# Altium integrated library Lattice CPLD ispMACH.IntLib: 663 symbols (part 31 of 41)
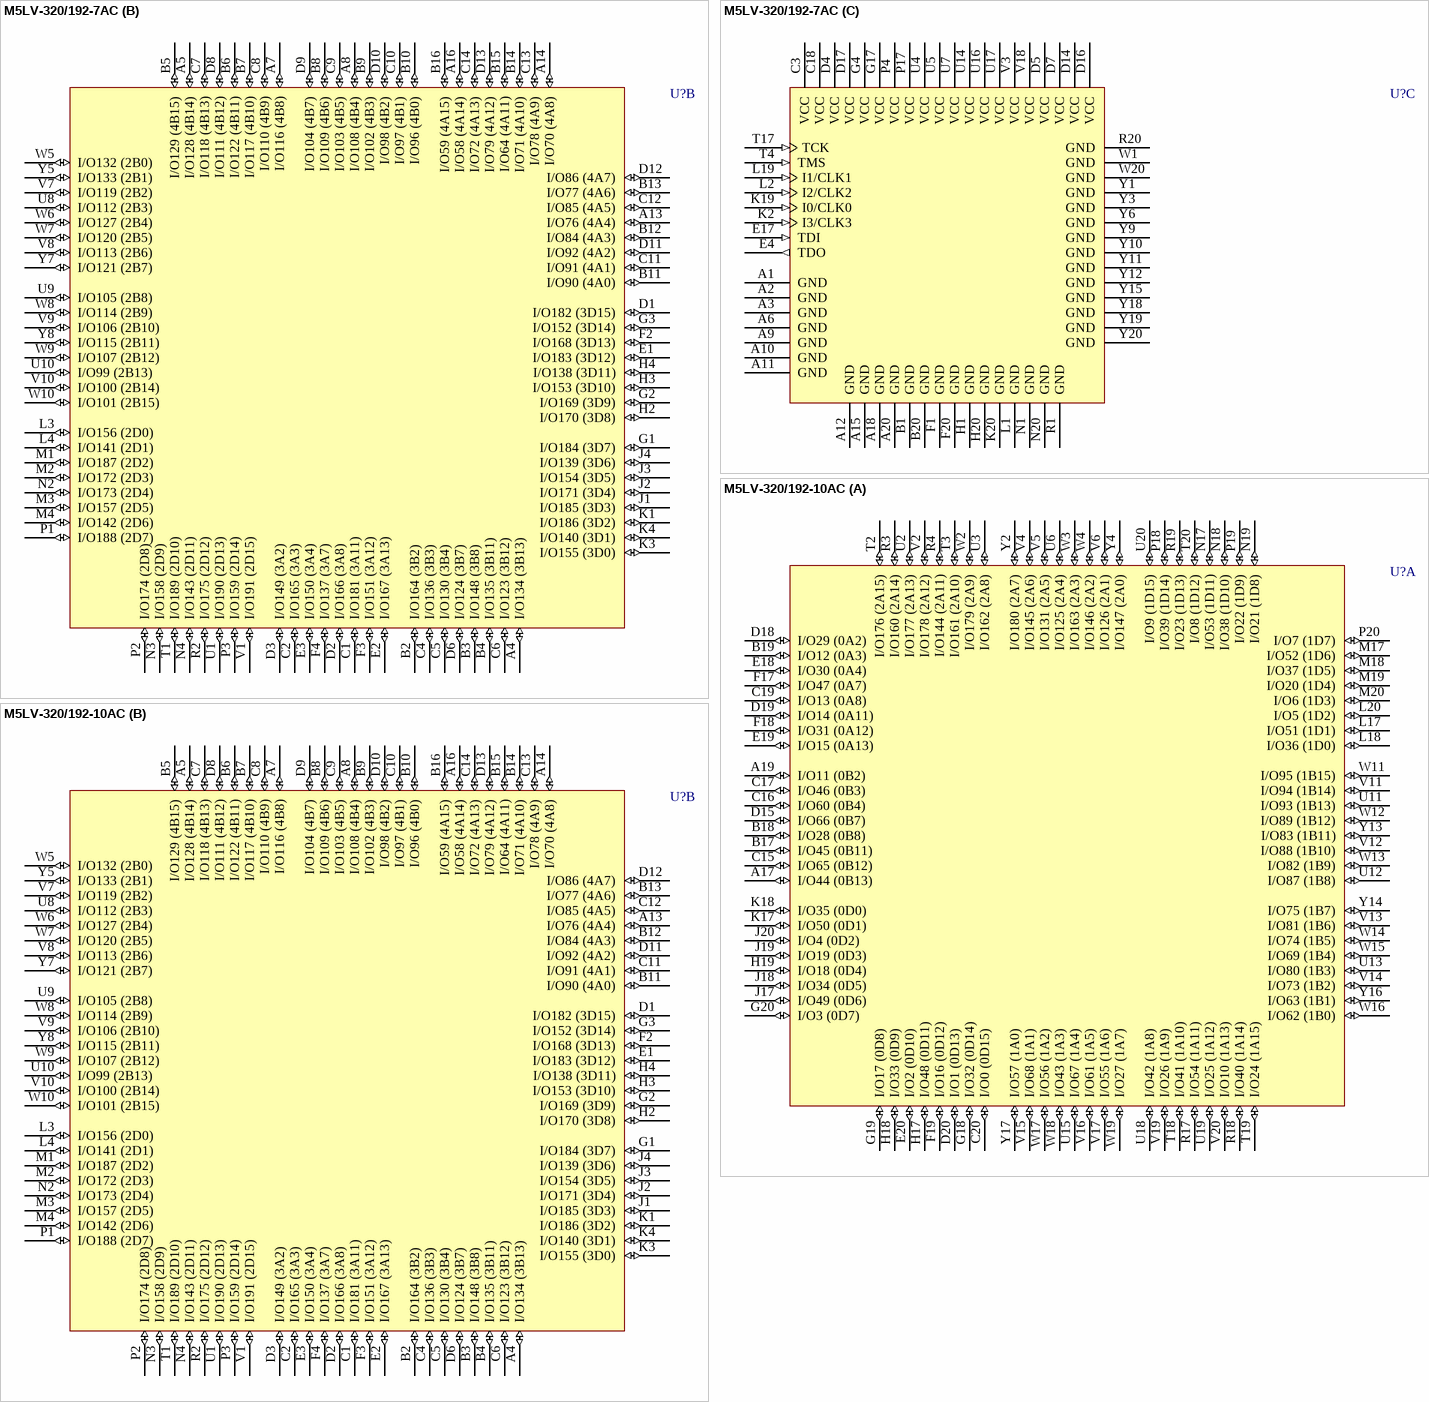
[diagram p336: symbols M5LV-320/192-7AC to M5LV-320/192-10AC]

## M5LV-320/192-7AC
designator U?
High-Density and High-I/O Complex PLD
footprint SBGA256 (BGA, 256-Leads, Body 27x27mm, Pitch 1.27mm)
3D model M5LV-SBGA256 (256-Ball Super Ball Grid Array (SBGA256))
part A pins: A17 I/O44 (0B13) (io), A19 I/O11 (0B2) (io), B17 I/O45 (0B11) (io), B18 I/O28 (0B8) (io), B19 I/O12 (0A3) (io), C15 I/O65 (0B12) (io), C16 I/O60 (0B4) (io), C17 I/O46 (0B3) (io), C19 I/O13 (0A8) (io), C20 I/O0 (0D15) (io), D15 I/O66 (0B7) (io), D18 I/O29 (0A2) (io), D19 I/O14 (0A11) (io), D20 I/O1 (0D13) (io), E18 I/O30 (0A4) (io), E19 I/O15 (0A13) (io), E20 I/O2 (0D10) (io), F17 I/O47 (0A7) (io), F18 I/O31 (0A12) (io), F19 I/O16 (0D12) (io), G18 I/O32 (0D14) (io), G19 I/O17 (0D8) (io), G20 I/O3 (0D7) (io), H17 I/O48 (0D11) (io), H18 I/O33 (0D9) (io), H19 I/O18 (0D4) (io), J17 I/O49 (0D6) (io), J18 I/O34 (0D5) (io), J19 I/O19 (0D3) (io), J20 I/O4 (0D2) (io), K17 I/O50 (0D1) (io), K18 I/O35 (0D0) (io), L17 I/O51 (1D1) (io), L18 I/O36 (1D0) (io), L20 I/O5 (1D2) (io), M17 I/O52 (1D6) (io), M18 I/O37 (1D5) (io), M19 I/O20 (1D4) (io), M20 I/O6 (1D3) (io), N17 I/O53 (1D11) (io), N18 I/O38 (1D10) (io), N19 I/O21 (1D8) (io), P18 I/O39 (1D14) (io), P19 I/O22 (1D9) (io), P20 I/O7 (1D7) (io), R3 I/O160 (2A14) (io), R4 I/O144 (2A11) (io), R17 I/O54 (1A11) (io), R18 I/O40 (1A14) (io), R19 I/O23 (1D13) (io), T2 I/O176 (2A15) (io), T3 I/O161 (2A10) (io), T18 I/O41 (1A10) (io), T19 I/O24 (1A15) (io), T20 I/O8 (1D12) (io), U2 I/O177 (2A13) (io), U3 I/O162 (2A8) (io), U6 I/O125 (2A4) (io), U11 I/O93 (1B13) (io), U12 I/O87 (1B8) (io), U13 I/O80 (1B3) (io), U15 I/O67 (1A4) (io), U18 I/O42 (1A8) (io), U19 I/O25 (1A12) (io), U20 I/O9 (1D15) (io), V2 I/O178 (2A12) (io), V4 I/O145 (2A6) (io), V5 I/O131 (2A5) (io), V6 I/O126 (2A1) (io), V11 I/O94 (1B14) (io), V12 I/O88 (1B10) (io), V13 I/O81 (1B6) (io), V14 I/O73 (1B2) (io), V15 I/O68 (1A1) (io), V16 I/O61 (1A5) (io), V17 I/O55 (1A6) (io), V19 I/O26 (1A9) (io), V20 I/O10 (1A13) (io), W2 I/O179 (2A9) (io), W3 I/O163 (2A3) (io), W4 I/O146 (2A2) (io), W11 I/O95 (1B15) (io), W12 I/O89 (1B12) (io), W13 I/O82 (1B9) (io), W14 I/O74 (1B5) (io), W15 I/O69 (1B4) (io), W16 I/O62 (1B0) (io), W17 I/O56 (1A2) (io), W18 I/O43 (1A3) (io), W19 I/O27 (1A7) (io), Y2 I/O180 (2A7) (io), Y4 I/O147 (2A0) (io), Y13 I/O83 (1B11) (io), Y14 I/O75 (1B7) (io), Y16 I/O63 (1B1) (io), Y17 I/O57 (1A0) (io)
part B pins: A4 I/O134 (3B13) (io), A5 I/O128 (4B14) (io), A7 I/O116 (4B8) (io), A8 I/O108 (4B4) (io), A13 I/O76 (4A4) (io), A14 I/O70 (4A8) (io), A16 I/O58 (4A14) (io), B2 I/O164 (3B2) (io), B3 I/O148 (3B8) (io), B4 I/O135 (3B11) (io), B5 I/O129 (4B15) (io), B6 I/O122 (4B11) (io), B7 I/O117 (4B10) (io), B8 I/O109 (4B6) (io), B9 I/O102 (4B3) (io), B10 I/O96 (4B0) (io), B11 I/O90 (4A0) (io), B12 I/O84 (4A3) (io), B13 I/O77 (4A6) (io), B14 I/O71 (4A10) (io), B15 I/O64 (4A11) (io), B16 I/O59 (4A15) (io), C1 I/O181 (3A11) (io), C2 I/O165 (3A3) (io), C4 I/O136 (3B3) (io), C5 I/O130 (3B4) (io), C6 I/O123 (3B12) (io), C7 I/O118 (4B13) (io), C8 I/O110 (4B9) (io), C9 I/O103 (4B5) (io), C10 I/O97 (4B1) (io), C11 I/O91 (4A1) (io), C12 I/O85 (4A5) (io), C13 I/O78 (4A9) (io), C14 I/O72 (4A13) (io), D1 I/O182 (3D15) (io), D2 I/O166 (3A8) (io), D3 I/O149 (3A2) (io), D6 I/O124 (3B7) (io), D8 I/O111 (4B12) (io), D9 I/O104 (4B7) (io), D10 I/O98 (4B2) (io), D11 I/O92 (4A2) (io), D12 I/O86 (4A7) (io), D13 I/O79 (4A12) (io), E1 I/O183 (3D12) (io), E2 I/O167 (3A13) (io), E3 I/O150 (3A4) (io), F2 I/O168 (3D13) (io), F3 I/O151 (3A12) (io), F4 I/O137 (3A7) (io), G1 I/O184 (3D7) (io), G2 I/O169 (3D9) (io), G3 I/O152 (3D14) (io), H2 I/O170 (3D8) (io), H3 I/O153 (3D10) (io), H4 I/O138 (3D11) (io), J1 I/O185 (3D3) (io), J2 I/O171 (3D4) (io), J3 I/O154 (3D5) (io), J4 I/O139 (3D6) (io), K1 I/O186 (3D2) (io), K3 I/O155 (3D0) (io), K4 I/O140 (3D1) (io), L3 I/O156 (2D0) (io), L4 I/O141 (2D1) (io), M1 I/O187 (2D2) (io), M2 I/O172 (2D3) (io), M3 I/O157 (2D5) (io), M4 I/O142 (2D6) (io), N2 I/O173 (2D4) (io), N3 I/O158 (2D9) (io), N4 I/O143 (2D11) (io), P1 I/O188 (2D7) (io), P2 I/O174 (2D8) (io), P3 I/O159 (2D14) (io), R2 I/O175 (2D12) (io), T1 I/O189 (2D10) (io), U1 I/O190 (2D13) (io), U8 I/O112 (2B3) (io), U9 I/O105 (2B8) (io), U10 I/O99 (2B13) (io), V1 I/O191 (2D15) (io), V7 I/O119 (2B2) (io), V8 I/O113 (2B6) (io), V9 I/O106 (2B10) (io), V10 I/O100 (2B14) (io), W5 I/O132 (2B0) (io), W6 I/O127 (2B4) (io), W7 I/O120 (2B5) (io), W8 I/O114 (2B9) (io), W9 I/O107 (2B12) (io), W10 I/O101 (2B15) (io), Y5 I/O133 (2B1) (io), Y7 I/O121 (2B7) (io), Y8 I/O115 (2B11) (io)
part C pins: A1 GND (power), A2 GND (power), A3 GND (power), A6 GND (power), A9 GND (power), A10 GND (power), A11 GND (power), A12 GND (power), A15 GND (power), A18 GND (power), A20 GND (power), B1 GND (power), B20 GND (power), C3 VCC (power), C18 VCC (power), D4 VCC (power), D5 VCC (power), D7 VCC (power), D14 VCC (power), D16 VCC (power), D17 VCC (power), E4 TDO (out), E17 TDI (in), F1 GND (power), F20 GND (power), G4 VCC (power), G17 VCC (power), H1 GND (power), H20 GND (power), K2 I3/CLK3 (in), K19 I0/CLK0 (in), K20 GND (power), L1 GND (power), L2 I2/CLK2 (in), L19 I1/CLK1 (in), N1 GND (power), N20 GND (power), P4 VCC (power), P17 VCC (power), R1 GND (power), R20 GND (power), T4 TMS (in), T17 TCK (in), U4 VCC (power), U5 VCC (power), U7 VCC (power), U14 VCC (power), U16 VCC (power), U17 VCC (power), V3 VCC (power), V18 VCC (power), W1 GND (power), W20 GND (power), Y1 GND (power), Y3 GND (power), Y6 GND (power), Y9 GND (power), Y10 GND (power), Y11 GND (power), Y12 GND (power), Y15 GND (power), Y18 GND (power), Y19 GND (power), Y20 GND (power)

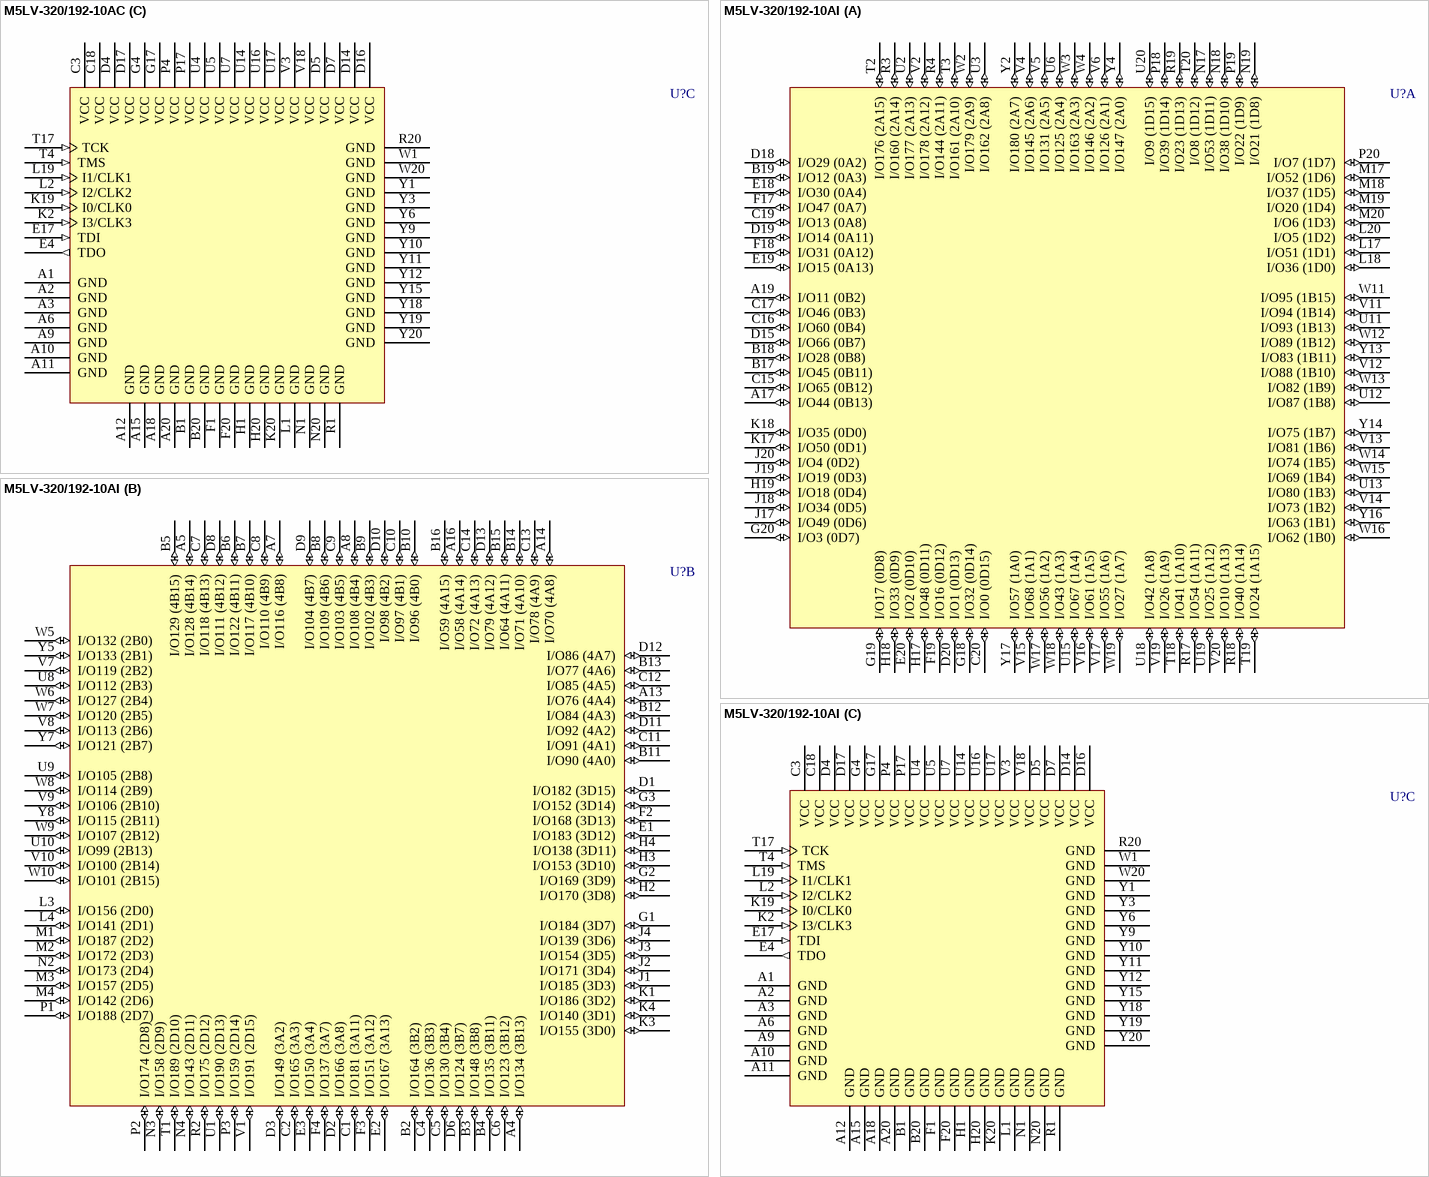
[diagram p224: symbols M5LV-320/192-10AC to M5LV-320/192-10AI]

## M5LV-320/192-10AC
designator U?
High-Density and High-I/O Complex PLD
footprint SBGA256 (BGA, 256-Leads, Body 27x27mm, Pitch 1.27mm)
3D model M5LV-SBGA256 (256-Ball Super Ball Grid Array (SBGA256))
part A pins: A17 I/O44 (0B13) (io), A19 I/O11 (0B2) (io), B17 I/O45 (0B11) (io), B18 I/O28 (0B8) (io), B19 I/O12 (0A3) (io), C15 I/O65 (0B12) (io), C16 I/O60 (0B4) (io), C17 I/O46 (0B3) (io), C19 I/O13 (0A8) (io), C20 I/O0 (0D15) (io), D15 I/O66 (0B7) (io), D18 I/O29 (0A2) (io), D19 I/O14 (0A11) (io), D20 I/O1 (0D13) (io), E18 I/O30 (0A4) (io), E19 I/O15 (0A13) (io), E20 I/O2 (0D10) (io), F17 I/O47 (0A7) (io), F18 I/O31 (0A12) (io), F19 I/O16 (0D12) (io), G18 I/O32 (0D14) (io), G19 I/O17 (0D8) (io), G20 I/O3 (0D7) (io), H17 I/O48 (0D11) (io), H18 I/O33 (0D9) (io), H19 I/O18 (0D4) (io), J17 I/O49 (0D6) (io), J18 I/O34 (0D5) (io), J19 I/O19 (0D3) (io), J20 I/O4 (0D2) (io), K17 I/O50 (0D1) (io), K18 I/O35 (0D0) (io), L17 I/O51 (1D1) (io), L18 I/O36 (1D0) (io), L20 I/O5 (1D2) (io), M17 I/O52 (1D6) (io), M18 I/O37 (1D5) (io), M19 I/O20 (1D4) (io), M20 I/O6 (1D3) (io), N17 I/O53 (1D11) (io), N18 I/O38 (1D10) (io), N19 I/O21 (1D8) (io), P18 I/O39 (1D14) (io), P19 I/O22 (1D9) (io), P20 I/O7 (1D7) (io), R3 I/O160 (2A14) (io), R4 I/O144 (2A11) (io), R17 I/O54 (1A11) (io), R18 I/O40 (1A14) (io), R19 I/O23 (1D13) (io), T2 I/O176 (2A15) (io), T3 I/O161 (2A10) (io), T18 I/O41 (1A10) (io), T19 I/O24 (1A15) (io), T20 I/O8 (1D12) (io), U2 I/O177 (2A13) (io), U3 I/O162 (2A8) (io), U6 I/O125 (2A4) (io), U11 I/O93 (1B13) (io), U12 I/O87 (1B8) (io), U13 I/O80 (1B3) (io), U15 I/O67 (1A4) (io), U18 I/O42 (1A8) (io), U19 I/O25 (1A12) (io), U20 I/O9 (1D15) (io), V2 I/O178 (2A12) (io), V4 I/O145 (2A6) (io), V5 I/O131 (2A5) (io), V6 I/O126 (2A1) (io), V11 I/O94 (1B14) (io), V12 I/O88 (1B10) (io), V13 I/O81 (1B6) (io), V14 I/O73 (1B2) (io), V15 I/O68 (1A1) (io), V16 I/O61 (1A5) (io), V17 I/O55 (1A6) (io), V19 I/O26 (1A9) (io), V20 I/O10 (1A13) (io), W2 I/O179 (2A9) (io), W3 I/O163 (2A3) (io), W4 I/O146 (2A2) (io), W11 I/O95 (1B15) (io), W12 I/O89 (1B12) (io), W13 I/O82 (1B9) (io), W14 I/O74 (1B5) (io), W15 I/O69 (1B4) (io), W16 I/O62 (1B0) (io), W17 I/O56 (1A2) (io), W18 I/O43 (1A3) (io), W19 I/O27 (1A7) (io), Y2 I/O180 (2A7) (io), Y4 I/O147 (2A0) (io), Y13 I/O83 (1B11) (io), Y14 I/O75 (1B7) (io), Y16 I/O63 (1B1) (io), Y17 I/O57 (1A0) (io)
part B pins: A4 I/O134 (3B13) (io), A5 I/O128 (4B14) (io), A7 I/O116 (4B8) (io), A8 I/O108 (4B4) (io), A13 I/O76 (4A4) (io), A14 I/O70 (4A8) (io), A16 I/O58 (4A14) (io), B2 I/O164 (3B2) (io), B3 I/O148 (3B8) (io), B4 I/O135 (3B11) (io), B5 I/O129 (4B15) (io), B6 I/O122 (4B11) (io), B7 I/O117 (4B10) (io), B8 I/O109 (4B6) (io), B9 I/O102 (4B3) (io), B10 I/O96 (4B0) (io), B11 I/O90 (4A0) (io), B12 I/O84 (4A3) (io), B13 I/O77 (4A6) (io), B14 I/O71 (4A10) (io), B15 I/O64 (4A11) (io), B16 I/O59 (4A15) (io), C1 I/O181 (3A11) (io), C2 I/O165 (3A3) (io), C4 I/O136 (3B3) (io), C5 I/O130 (3B4) (io), C6 I/O123 (3B12) (io), C7 I/O118 (4B13) (io), C8 I/O110 (4B9) (io), C9 I/O103 (4B5) (io), C10 I/O97 (4B1) (io), C11 I/O91 (4A1) (io), C12 I/O85 (4A5) (io), C13 I/O78 (4A9) (io), C14 I/O72 (4A13) (io), D1 I/O182 (3D15) (io), D2 I/O166 (3A8) (io), D3 I/O149 (3A2) (io), D6 I/O124 (3B7) (io), D8 I/O111 (4B12) (io), D9 I/O104 (4B7) (io), D10 I/O98 (4B2) (io), D11 I/O92 (4A2) (io), D12 I/O86 (4A7) (io), D13 I/O79 (4A12) (io), E1 I/O183 (3D12) (io), E2 I/O167 (3A13) (io), E3 I/O150 (3A4) (io), F2 I/O168 (3D13) (io), F3 I/O151 (3A12) (io), F4 I/O137 (3A7) (io), G1 I/O184 (3D7) (io), G2 I/O169 (3D9) (io), G3 I/O152 (3D14) (io), H2 I/O170 (3D8) (io), H3 I/O153 (3D10) (io), H4 I/O138 (3D11) (io), J1 I/O185 (3D3) (io), J2 I/O171 (3D4) (io), J3 I/O154 (3D5) (io), J4 I/O139 (3D6) (io), K1 I/O186 (3D2) (io), K3 I/O155 (3D0) (io), K4 I/O140 (3D1) (io), L3 I/O156 (2D0) (io), L4 I/O141 (2D1) (io), M1 I/O187 (2D2) (io), M2 I/O172 (2D3) (io), M3 I/O157 (2D5) (io), M4 I/O142 (2D6) (io), N2 I/O173 (2D4) (io), N3 I/O158 (2D9) (io), N4 I/O143 (2D11) (io), P1 I/O188 (2D7) (io), P2 I/O174 (2D8) (io), P3 I/O159 (2D14) (io), R2 I/O175 (2D12) (io), T1 I/O189 (2D10) (io), U1 I/O190 (2D13) (io), U8 I/O112 (2B3) (io), U9 I/O105 (2B8) (io), U10 I/O99 (2B13) (io), V1 I/O191 (2D15) (io), V7 I/O119 (2B2) (io), V8 I/O113 (2B6) (io), V9 I/O106 (2B10) (io), V10 I/O100 (2B14) (io), W5 I/O132 (2B0) (io), W6 I/O127 (2B4) (io), W7 I/O120 (2B5) (io), W8 I/O114 (2B9) (io), W9 I/O107 (2B12) (io), W10 I/O101 (2B15) (io), Y5 I/O133 (2B1) (io), Y7 I/O121 (2B7) (io), Y8 I/O115 (2B11) (io)
part C pins: A1 GND (power), A2 GND (power), A3 GND (power), A6 GND (power), A9 GND (power), A10 GND (power), A11 GND (power), A12 GND (power), A15 GND (power), A18 GND (power), A20 GND (power), B1 GND (power), B20 GND (power), C3 VCC (power), C18 VCC (power), D4 VCC (power), D5 VCC (power), D7 VCC (power), D14 VCC (power), D16 VCC (power), D17 VCC (power), E4 TDO (out), E17 TDI (in), F1 GND (power), F20 GND (power), G4 VCC (power), G17 VCC (power), H1 GND (power), H20 GND (power), K2 I3/CLK3 (in), K19 I0/CLK0 (in), K20 GND (power), L1 GND (power), L2 I2/CLK2 (in), L19 I1/CLK1 (in), N1 GND (power), N20 GND (power), P4 VCC (power), P17 VCC (power), R1 GND (power), R20 GND (power), T4 TMS (in), T17 TCK (in), U4 VCC (power), U5 VCC (power), U7 VCC (power), U14 VCC (power), U16 VCC (power), U17 VCC (power), V3 VCC (power), V18 VCC (power), W1 GND (power), W20 GND (power), Y1 GND (power), Y3 GND (power), Y6 GND (power), Y9 GND (power), Y10 GND (power), Y11 GND (power), Y12 GND (power), Y15 GND (power), Y18 GND (power), Y19 GND (power), Y20 GND (power)

## M5LV-320/192-10AI
designator U?
High-Density and High-I/O Complex PLD
footprint SBGA256 (BGA, 256-Leads, Body 27x27mm, Pitch 1.27mm)
3D model M5LV-SBGA256 (256-Ball Super Ball Grid Array (SBGA256))
part A pins: A17 I/O44 (0B13) (io), A19 I/O11 (0B2) (io), B17 I/O45 (0B11) (io), B18 I/O28 (0B8) (io), B19 I/O12 (0A3) (io), C15 I/O65 (0B12) (io), C16 I/O60 (0B4) (io), C17 I/O46 (0B3) (io), C19 I/O13 (0A8) (io), C20 I/O0 (0D15) (io), D15 I/O66 (0B7) (io), D18 I/O29 (0A2) (io), D19 I/O14 (0A11) (io), D20 I/O1 (0D13) (io), E18 I/O30 (0A4) (io), E19 I/O15 (0A13) (io), E20 I/O2 (0D10) (io), F17 I/O47 (0A7) (io), F18 I/O31 (0A12) (io), F19 I/O16 (0D12) (io), G18 I/O32 (0D14) (io), G19 I/O17 (0D8) (io), G20 I/O3 (0D7) (io), H17 I/O48 (0D11) (io), H18 I/O33 (0D9) (io), H19 I/O18 (0D4) (io), J17 I/O49 (0D6) (io), J18 I/O34 (0D5) (io), J19 I/O19 (0D3) (io), J20 I/O4 (0D2) (io), K17 I/O50 (0D1) (io), K18 I/O35 (0D0) (io), L17 I/O51 (1D1) (io), L18 I/O36 (1D0) (io), L20 I/O5 (1D2) (io), M17 I/O52 (1D6) (io), M18 I/O37 (1D5) (io), M19 I/O20 (1D4) (io), M20 I/O6 (1D3) (io), N17 I/O53 (1D11) (io), N18 I/O38 (1D10) (io), N19 I/O21 (1D8) (io), P18 I/O39 (1D14) (io), P19 I/O22 (1D9) (io), P20 I/O7 (1D7) (io), R3 I/O160 (2A14) (io), R4 I/O144 (2A11) (io), R17 I/O54 (1A11) (io), R18 I/O40 (1A14) (io), R19 I/O23 (1D13) (io), T2 I/O176 (2A15) (io), T3 I/O161 (2A10) (io), T18 I/O41 (1A10) (io), T19 I/O24 (1A15) (io), T20 I/O8 (1D12) (io), U2 I/O177 (2A13) (io), U3 I/O162 (2A8) (io), U6 I/O125 (2A4) (io), U11 I/O93 (1B13) (io), U12 I/O87 (1B8) (io), U13 I/O80 (1B3) (io), U15 I/O67 (1A4) (io), U18 I/O42 (1A8) (io), U19 I/O25 (1A12) (io), U20 I/O9 (1D15) (io), V2 I/O178 (2A12) (io), V4 I/O145 (2A6) (io), V5 I/O131 (2A5) (io), V6 I/O126 (2A1) (io), V11 I/O94 (1B14) (io), V12 I/O88 (1B10) (io), V13 I/O81 (1B6) (io), V14 I/O73 (1B2) (io), V15 I/O68 (1A1) (io), V16 I/O61 (1A5) (io), V17 I/O55 (1A6) (io), V19 I/O26 (1A9) (io), V20 I/O10 (1A13) (io), W2 I/O179 (2A9) (io), W3 I/O163 (2A3) (io), W4 I/O146 (2A2) (io), W11 I/O95 (1B15) (io), W12 I/O89 (1B12) (io), W13 I/O82 (1B9) (io), W14 I/O74 (1B5) (io), W15 I/O69 (1B4) (io), W16 I/O62 (1B0) (io), W17 I/O56 (1A2) (io), W18 I/O43 (1A3) (io), W19 I/O27 (1A7) (io), Y2 I/O180 (2A7) (io), Y4 I/O147 (2A0) (io), Y13 I/O83 (1B11) (io), Y14 I/O75 (1B7) (io), Y16 I/O63 (1B1) (io), Y17 I/O57 (1A0) (io)
part B pins: A4 I/O134 (3B13) (io), A5 I/O128 (4B14) (io), A7 I/O116 (4B8) (io), A8 I/O108 (4B4) (io), A13 I/O76 (4A4) (io), A14 I/O70 (4A8) (io), A16 I/O58 (4A14) (io), B2 I/O164 (3B2) (io), B3 I/O148 (3B8) (io), B4 I/O135 (3B11) (io), B5 I/O129 (4B15) (io), B6 I/O122 (4B11) (io), B7 I/O117 (4B10) (io), B8 I/O109 (4B6) (io), B9 I/O102 (4B3) (io), B10 I/O96 (4B0) (io), B11 I/O90 (4A0) (io), B12 I/O84 (4A3) (io), B13 I/O77 (4A6) (io), B14 I/O71 (4A10) (io), B15 I/O64 (4A11) (io), B16 I/O59 (4A15) (io), C1 I/O181 (3A11) (io), C2 I/O165 (3A3) (io), C4 I/O136 (3B3) (io), C5 I/O130 (3B4) (io), C6 I/O123 (3B12) (io), C7 I/O118 (4B13) (io), C8 I/O110 (4B9) (io), C9 I/O103 (4B5) (io), C10 I/O97 (4B1) (io), C11 I/O91 (4A1) (io), C12 I/O85 (4A5) (io), C13 I/O78 (4A9) (io), C14 I/O72 (4A13) (io), D1 I/O182 (3D15) (io), D2 I/O166 (3A8) (io), D3 I/O149 (3A2) (io), D6 I/O124 (3B7) (io), D8 I/O111 (4B12) (io), D9 I/O104 (4B7) (io), D10 I/O98 (4B2) (io), D11 I/O92 (4A2) (io), D12 I/O86 (4A7) (io), D13 I/O79 (4A12) (io), E1 I/O183 (3D12) (io), E2 I/O167 (3A13) (io), E3 I/O150 (3A4) (io), F2 I/O168 (3D13) (io), F3 I/O151 (3A12) (io), F4 I/O137 (3A7) (io), G1 I/O184 (3D7) (io), G2 I/O169 (3D9) (io), G3 I/O152 (3D14) (io), H2 I/O170 (3D8) (io), H3 I/O153 (3D10) (io), H4 I/O138 (3D11) (io), J1 I/O185 (3D3) (io), J2 I/O171 (3D4) (io), J3 I/O154 (3D5) (io), J4 I/O139 (3D6) (io), K1 I/O186 (3D2) (io), K3 I/O155 (3D0) (io), K4 I/O140 (3D1) (io), L3 I/O156 (2D0) (io), L4 I/O141 (2D1) (io), M1 I/O187 (2D2) (io), M2 I/O172 (2D3) (io), M3 I/O157 (2D5) (io), M4 I/O142 (2D6) (io), N2 I/O173 (2D4) (io), N3 I/O158 (2D9) (io), N4 I/O143 (2D11) (io), P1 I/O188 (2D7) (io), P2 I/O174 (2D8) (io), P3 I/O159 (2D14) (io), R2 I/O175 (2D12) (io), T1 I/O189 (2D10) (io), U1 I/O190 (2D13) (io), U8 I/O112 (2B3) (io), U9 I/O105 (2B8) (io), U10 I/O99 (2B13) (io), V1 I/O191 (2D15) (io), V7 I/O119 (2B2) (io), V8 I/O113 (2B6) (io), V9 I/O106 (2B10) (io), V10 I/O100 (2B14) (io), W5 I/O132 (2B0) (io), W6 I/O127 (2B4) (io), W7 I/O120 (2B5) (io), W8 I/O114 (2B9) (io), W9 I/O107 (2B12) (io), W10 I/O101 (2B15) (io), Y5 I/O133 (2B1) (io), Y7 I/O121 (2B7) (io), Y8 I/O115 (2B11) (io)
part C pins: A1 GND (power), A2 GND (power), A3 GND (power), A6 GND (power), A9 GND (power), A10 GND (power), A11 GND (power), A12 GND (power), A15 GND (power), A18 GND (power), A20 GND (power), B1 GND (power), B20 GND (power), C3 VCC (power), C18 VCC (power), D4 VCC (power), D5 VCC (power), D7 VCC (power), D14 VCC (power), D16 VCC (power), D17 VCC (power), E4 TDO (out), E17 TDI (in), F1 GND (power), F20 GND (power), G4 VCC (power), G17 VCC (power), H1 GND (power), H20 GND (power), K2 I3/CLK3 (in), K19 I0/CLK0 (in), K20 GND (power), L1 GND (power), L2 I2/CLK2 (in), L19 I1/CLK1 (in), N1 GND (power), N20 GND (power), P4 VCC (power), P17 VCC (power), R1 GND (power), R20 GND (power), T4 TMS (in), T17 TCK (in), U4 VCC (power), U5 VCC (power), U7 VCC (power), U14 VCC (power), U16 VCC (power), U17 VCC (power), V3 VCC (power), V18 VCC (power), W1 GND (power), W20 GND (power), Y1 GND (power), Y3 GND (power), Y6 GND (power), Y9 GND (power), Y10 GND (power), Y11 GND (power), Y12 GND (power), Y15 GND (power), Y18 GND (power), Y19 GND (power), Y20 GND (power)

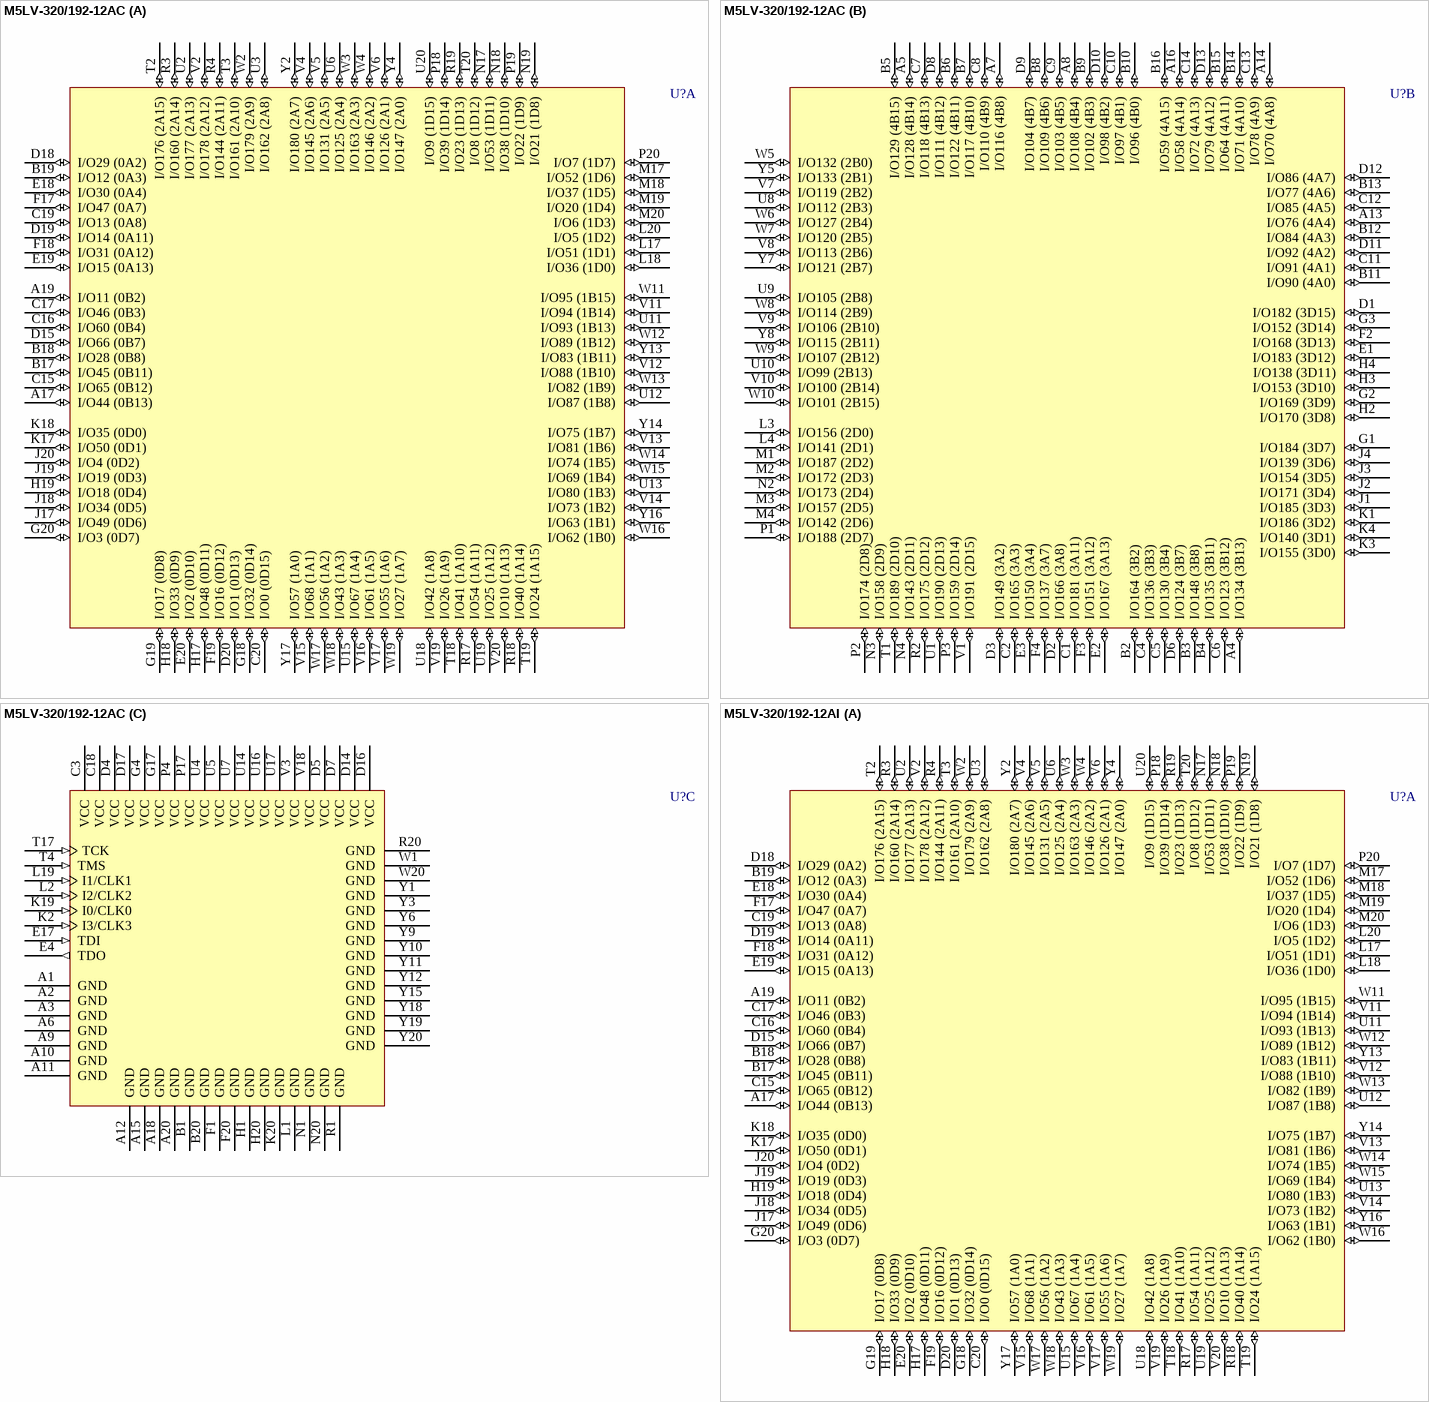
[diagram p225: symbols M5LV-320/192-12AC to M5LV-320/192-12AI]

## M5LV-320/192-12AC
designator U?
High-Density and High-I/O Complex PLD
footprint SBGA256 (BGA, 256-Leads, Body 27x27mm, Pitch 1.27mm)
3D model M5LV-SBGA256 (256-Ball Super Ball Grid Array (SBGA256))
part A pins: A17 I/O44 (0B13) (io), A19 I/O11 (0B2) (io), B17 I/O45 (0B11) (io), B18 I/O28 (0B8) (io), B19 I/O12 (0A3) (io), C15 I/O65 (0B12) (io), C16 I/O60 (0B4) (io), C17 I/O46 (0B3) (io), C19 I/O13 (0A8) (io), C20 I/O0 (0D15) (io), D15 I/O66 (0B7) (io), D18 I/O29 (0A2) (io), D19 I/O14 (0A11) (io), D20 I/O1 (0D13) (io), E18 I/O30 (0A4) (io), E19 I/O15 (0A13) (io), E20 I/O2 (0D10) (io), F17 I/O47 (0A7) (io), F18 I/O31 (0A12) (io), F19 I/O16 (0D12) (io), G18 I/O32 (0D14) (io), G19 I/O17 (0D8) (io), G20 I/O3 (0D7) (io), H17 I/O48 (0D11) (io), H18 I/O33 (0D9) (io), H19 I/O18 (0D4) (io), J17 I/O49 (0D6) (io), J18 I/O34 (0D5) (io), J19 I/O19 (0D3) (io), J20 I/O4 (0D2) (io), K17 I/O50 (0D1) (io), K18 I/O35 (0D0) (io), L17 I/O51 (1D1) (io), L18 I/O36 (1D0) (io), L20 I/O5 (1D2) (io), M17 I/O52 (1D6) (io), M18 I/O37 (1D5) (io), M19 I/O20 (1D4) (io), M20 I/O6 (1D3) (io), N17 I/O53 (1D11) (io), N18 I/O38 (1D10) (io), N19 I/O21 (1D8) (io), P18 I/O39 (1D14) (io), P19 I/O22 (1D9) (io), P20 I/O7 (1D7) (io), R3 I/O160 (2A14) (io), R4 I/O144 (2A11) (io), R17 I/O54 (1A11) (io), R18 I/O40 (1A14) (io), R19 I/O23 (1D13) (io), T2 I/O176 (2A15) (io), T3 I/O161 (2A10) (io), T18 I/O41 (1A10) (io), T19 I/O24 (1A15) (io), T20 I/O8 (1D12) (io), U2 I/O177 (2A13) (io), U3 I/O162 (2A8) (io), U6 I/O125 (2A4) (io), U11 I/O93 (1B13) (io), U12 I/O87 (1B8) (io), U13 I/O80 (1B3) (io), U15 I/O67 (1A4) (io), U18 I/O42 (1A8) (io), U19 I/O25 (1A12) (io), U20 I/O9 (1D15) (io), V2 I/O178 (2A12) (io), V4 I/O145 (2A6) (io), V5 I/O131 (2A5) (io), V6 I/O126 (2A1) (io), V11 I/O94 (1B14) (io), V12 I/O88 (1B10) (io), V13 I/O81 (1B6) (io), V14 I/O73 (1B2) (io), V15 I/O68 (1A1) (io), V16 I/O61 (1A5) (io), V17 I/O55 (1A6) (io), V19 I/O26 (1A9) (io), V20 I/O10 (1A13) (io), W2 I/O179 (2A9) (io), W3 I/O163 (2A3) (io), W4 I/O146 (2A2) (io), W11 I/O95 (1B15) (io), W12 I/O89 (1B12) (io), W13 I/O82 (1B9) (io), W14 I/O74 (1B5) (io), W15 I/O69 (1B4) (io), W16 I/O62 (1B0) (io), W17 I/O56 (1A2) (io), W18 I/O43 (1A3) (io), W19 I/O27 (1A7) (io), Y2 I/O180 (2A7) (io), Y4 I/O147 (2A0) (io), Y13 I/O83 (1B11) (io), Y14 I/O75 (1B7) (io), Y16 I/O63 (1B1) (io), Y17 I/O57 (1A0) (io)
part B pins: A4 I/O134 (3B13) (io), A5 I/O128 (4B14) (io), A7 I/O116 (4B8) (io), A8 I/O108 (4B4) (io), A13 I/O76 (4A4) (io), A14 I/O70 (4A8) (io), A16 I/O58 (4A14) (io), B2 I/O164 (3B2) (io), B3 I/O148 (3B8) (io), B4 I/O135 (3B11) (io), B5 I/O129 (4B15) (io), B6 I/O122 (4B11) (io), B7 I/O117 (4B10) (io), B8 I/O109 (4B6) (io), B9 I/O102 (4B3) (io), B10 I/O96 (4B0) (io), B11 I/O90 (4A0) (io), B12 I/O84 (4A3) (io), B13 I/O77 (4A6) (io), B14 I/O71 (4A10) (io), B15 I/O64 (4A11) (io), B16 I/O59 (4A15) (io), C1 I/O181 (3A11) (io), C2 I/O165 (3A3) (io), C4 I/O136 (3B3) (io), C5 I/O130 (3B4) (io), C6 I/O123 (3B12) (io), C7 I/O118 (4B13) (io), C8 I/O110 (4B9) (io), C9 I/O103 (4B5) (io), C10 I/O97 (4B1) (io), C11 I/O91 (4A1) (io), C12 I/O85 (4A5) (io), C13 I/O78 (4A9) (io), C14 I/O72 (4A13) (io), D1 I/O182 (3D15) (io), D2 I/O166 (3A8) (io), D3 I/O149 (3A2) (io), D6 I/O124 (3B7) (io), D8 I/O111 (4B12) (io), D9 I/O104 (4B7) (io), D10 I/O98 (4B2) (io), D11 I/O92 (4A2) (io), D12 I/O86 (4A7) (io), D13 I/O79 (4A12) (io), E1 I/O183 (3D12) (io), E2 I/O167 (3A13) (io), E3 I/O150 (3A4) (io), F2 I/O168 (3D13) (io), F3 I/O151 (3A12) (io), F4 I/O137 (3A7) (io), G1 I/O184 (3D7) (io), G2 I/O169 (3D9) (io), G3 I/O152 (3D14) (io), H2 I/O170 (3D8) (io), H3 I/O153 (3D10) (io), H4 I/O138 (3D11) (io), J1 I/O185 (3D3) (io), J2 I/O171 (3D4) (io), J3 I/O154 (3D5) (io), J4 I/O139 (3D6) (io), K1 I/O186 (3D2) (io), K3 I/O155 (3D0) (io), K4 I/O140 (3D1) (io), L3 I/O156 (2D0) (io), L4 I/O141 (2D1) (io), M1 I/O187 (2D2) (io), M2 I/O172 (2D3) (io), M3 I/O157 (2D5) (io), M4 I/O142 (2D6) (io), N2 I/O173 (2D4) (io), N3 I/O158 (2D9) (io), N4 I/O143 (2D11) (io), P1 I/O188 (2D7) (io), P2 I/O174 (2D8) (io), P3 I/O159 (2D14) (io), R2 I/O175 (2D12) (io), T1 I/O189 (2D10) (io), U1 I/O190 (2D13) (io), U8 I/O112 (2B3) (io), U9 I/O105 (2B8) (io), U10 I/O99 (2B13) (io), V1 I/O191 (2D15) (io), V7 I/O119 (2B2) (io), V8 I/O113 (2B6) (io), V9 I/O106 (2B10) (io), V10 I/O100 (2B14) (io), W5 I/O132 (2B0) (io), W6 I/O127 (2B4) (io), W7 I/O120 (2B5) (io), W8 I/O114 (2B9) (io), W9 I/O107 (2B12) (io), W10 I/O101 (2B15) (io), Y5 I/O133 (2B1) (io), Y7 I/O121 (2B7) (io), Y8 I/O115 (2B11) (io)
part C pins: A1 GND (power), A2 GND (power), A3 GND (power), A6 GND (power), A9 GND (power), A10 GND (power), A11 GND (power), A12 GND (power), A15 GND (power), A18 GND (power), A20 GND (power), B1 GND (power), B20 GND (power), C3 VCC (power), C18 VCC (power), D4 VCC (power), D5 VCC (power), D7 VCC (power), D14 VCC (power), D16 VCC (power), D17 VCC (power), E4 TDO (out), E17 TDI (in), F1 GND (power), F20 GND (power), G4 VCC (power), G17 VCC (power), H1 GND (power), H20 GND (power), K2 I3/CLK3 (in), K19 I0/CLK0 (in), K20 GND (power), L1 GND (power), L2 I2/CLK2 (in), L19 I1/CLK1 (in), N1 GND (power), N20 GND (power), P4 VCC (power), P17 VCC (power), R1 GND (power), R20 GND (power), T4 TMS (in), T17 TCK (in), U4 VCC (power), U5 VCC (power), U7 VCC (power), U14 VCC (power), U16 VCC (power), U17 VCC (power), V3 VCC (power), V18 VCC (power), W1 GND (power), W20 GND (power), Y1 GND (power), Y3 GND (power), Y6 GND (power), Y9 GND (power), Y10 GND (power), Y11 GND (power), Y12 GND (power), Y15 GND (power), Y18 GND (power), Y19 GND (power), Y20 GND (power)

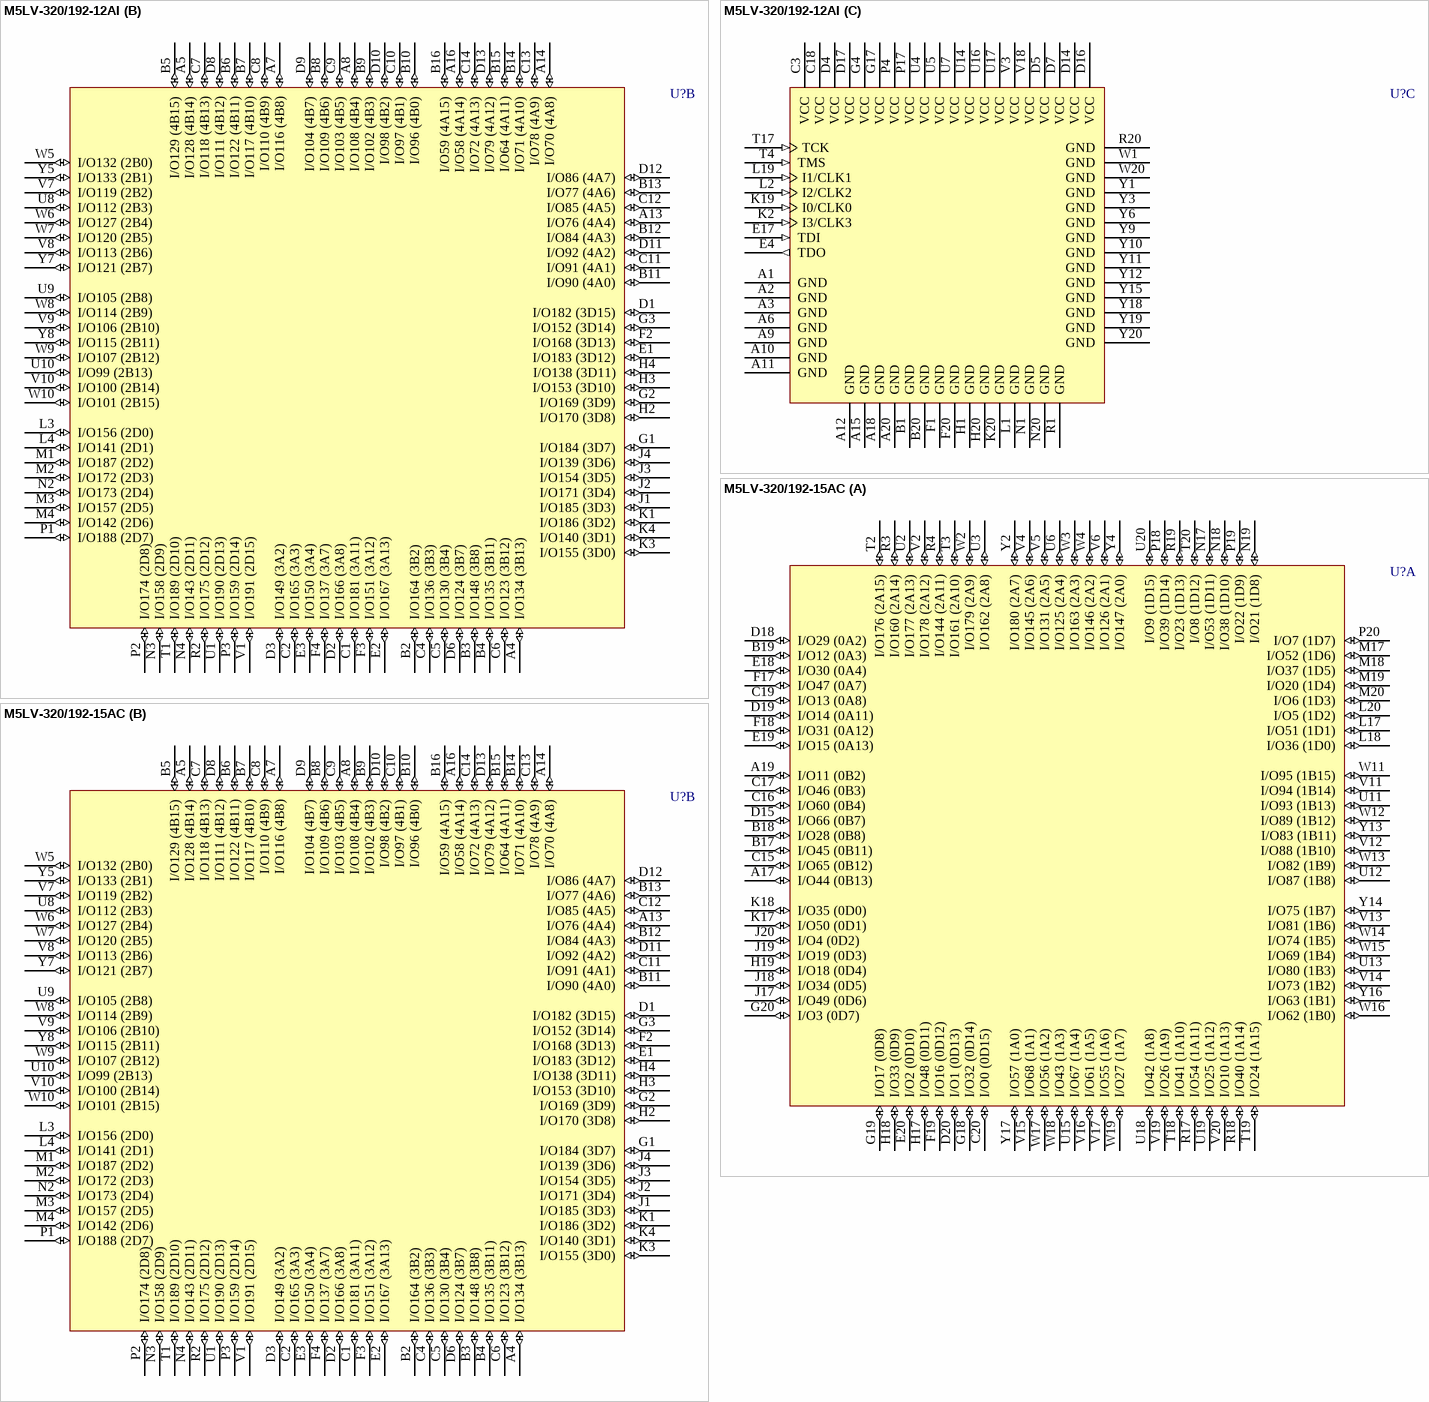
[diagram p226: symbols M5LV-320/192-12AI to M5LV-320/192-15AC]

## M5LV-320/192-12AI
designator U?
High-Density and High-I/O Complex PLD
footprint SBGA256 (BGA, 256-Leads, Body 27x27mm, Pitch 1.27mm)
3D model M5LV-SBGA256 (256-Ball Super Ball Grid Array (SBGA256))
part A pins: A17 I/O44 (0B13) (io), A19 I/O11 (0B2) (io), B17 I/O45 (0B11) (io), B18 I/O28 (0B8) (io), B19 I/O12 (0A3) (io), C15 I/O65 (0B12) (io), C16 I/O60 (0B4) (io), C17 I/O46 (0B3) (io), C19 I/O13 (0A8) (io), C20 I/O0 (0D15) (io), D15 I/O66 (0B7) (io), D18 I/O29 (0A2) (io), D19 I/O14 (0A11) (io), D20 I/O1 (0D13) (io), E18 I/O30 (0A4) (io), E19 I/O15 (0A13) (io), E20 I/O2 (0D10) (io), F17 I/O47 (0A7) (io), F18 I/O31 (0A12) (io), F19 I/O16 (0D12) (io), G18 I/O32 (0D14) (io), G19 I/O17 (0D8) (io), G20 I/O3 (0D7) (io), H17 I/O48 (0D11) (io), H18 I/O33 (0D9) (io), H19 I/O18 (0D4) (io), J17 I/O49 (0D6) (io), J18 I/O34 (0D5) (io), J19 I/O19 (0D3) (io), J20 I/O4 (0D2) (io), K17 I/O50 (0D1) (io), K18 I/O35 (0D0) (io), L17 I/O51 (1D1) (io), L18 I/O36 (1D0) (io), L20 I/O5 (1D2) (io), M17 I/O52 (1D6) (io), M18 I/O37 (1D5) (io), M19 I/O20 (1D4) (io), M20 I/O6 (1D3) (io), N17 I/O53 (1D11) (io), N18 I/O38 (1D10) (io), N19 I/O21 (1D8) (io), P18 I/O39 (1D14) (io), P19 I/O22 (1D9) (io), P20 I/O7 (1D7) (io), R3 I/O160 (2A14) (io), R4 I/O144 (2A11) (io), R17 I/O54 (1A11) (io), R18 I/O40 (1A14) (io), R19 I/O23 (1D13) (io), T2 I/O176 (2A15) (io), T3 I/O161 (2A10) (io), T18 I/O41 (1A10) (io), T19 I/O24 (1A15) (io), T20 I/O8 (1D12) (io), U2 I/O177 (2A13) (io), U3 I/O162 (2A8) (io), U6 I/O125 (2A4) (io), U11 I/O93 (1B13) (io), U12 I/O87 (1B8) (io), U13 I/O80 (1B3) (io), U15 I/O67 (1A4) (io), U18 I/O42 (1A8) (io), U19 I/O25 (1A12) (io), U20 I/O9 (1D15) (io), V2 I/O178 (2A12) (io), V4 I/O145 (2A6) (io), V5 I/O131 (2A5) (io), V6 I/O126 (2A1) (io), V11 I/O94 (1B14) (io), V12 I/O88 (1B10) (io), V13 I/O81 (1B6) (io), V14 I/O73 (1B2) (io), V15 I/O68 (1A1) (io), V16 I/O61 (1A5) (io), V17 I/O55 (1A6) (io), V19 I/O26 (1A9) (io), V20 I/O10 (1A13) (io), W2 I/O179 (2A9) (io), W3 I/O163 (2A3) (io), W4 I/O146 (2A2) (io), W11 I/O95 (1B15) (io), W12 I/O89 (1B12) (io), W13 I/O82 (1B9) (io), W14 I/O74 (1B5) (io), W15 I/O69 (1B4) (io), W16 I/O62 (1B0) (io), W17 I/O56 (1A2) (io), W18 I/O43 (1A3) (io), W19 I/O27 (1A7) (io), Y2 I/O180 (2A7) (io), Y4 I/O147 (2A0) (io), Y13 I/O83 (1B11) (io), Y14 I/O75 (1B7) (io), Y16 I/O63 (1B1) (io), Y17 I/O57 (1A0) (io)
part B pins: A4 I/O134 (3B13) (io), A5 I/O128 (4B14) (io), A7 I/O116 (4B8) (io), A8 I/O108 (4B4) (io), A13 I/O76 (4A4) (io), A14 I/O70 (4A8) (io), A16 I/O58 (4A14) (io), B2 I/O164 (3B2) (io), B3 I/O148 (3B8) (io), B4 I/O135 (3B11) (io), B5 I/O129 (4B15) (io), B6 I/O122 (4B11) (io), B7 I/O117 (4B10) (io), B8 I/O109 (4B6) (io), B9 I/O102 (4B3) (io), B10 I/O96 (4B0) (io), B11 I/O90 (4A0) (io), B12 I/O84 (4A3) (io), B13 I/O77 (4A6) (io), B14 I/O71 (4A10) (io), B15 I/O64 (4A11) (io), B16 I/O59 (4A15) (io), C1 I/O181 (3A11) (io), C2 I/O165 (3A3) (io), C4 I/O136 (3B3) (io), C5 I/O130 (3B4) (io), C6 I/O123 (3B12) (io), C7 I/O118 (4B13) (io), C8 I/O110 (4B9) (io), C9 I/O103 (4B5) (io), C10 I/O97 (4B1) (io), C11 I/O91 (4A1) (io), C12 I/O85 (4A5) (io), C13 I/O78 (4A9) (io), C14 I/O72 (4A13) (io), D1 I/O182 (3D15) (io), D2 I/O166 (3A8) (io), D3 I/O149 (3A2) (io), D6 I/O124 (3B7) (io), D8 I/O111 (4B12) (io), D9 I/O104 (4B7) (io), D10 I/O98 (4B2) (io), D11 I/O92 (4A2) (io), D12 I/O86 (4A7) (io), D13 I/O79 (4A12) (io), E1 I/O183 (3D12) (io), E2 I/O167 (3A13) (io), E3 I/O150 (3A4) (io), F2 I/O168 (3D13) (io), F3 I/O151 (3A12) (io), F4 I/O137 (3A7) (io), G1 I/O184 (3D7) (io), G2 I/O169 (3D9) (io), G3 I/O152 (3D14) (io), H2 I/O170 (3D8) (io), H3 I/O153 (3D10) (io), H4 I/O138 (3D11) (io), J1 I/O185 (3D3) (io), J2 I/O171 (3D4) (io), J3 I/O154 (3D5) (io), J4 I/O139 (3D6) (io), K1 I/O186 (3D2) (io), K3 I/O155 (3D0) (io), K4 I/O140 (3D1) (io), L3 I/O156 (2D0) (io), L4 I/O141 (2D1) (io), M1 I/O187 (2D2) (io), M2 I/O172 (2D3) (io), M3 I/O157 (2D5) (io), M4 I/O142 (2D6) (io), N2 I/O173 (2D4) (io), N3 I/O158 (2D9) (io), N4 I/O143 (2D11) (io), P1 I/O188 (2D7) (io), P2 I/O174 (2D8) (io), P3 I/O159 (2D14) (io), R2 I/O175 (2D12) (io), T1 I/O189 (2D10) (io), U1 I/O190 (2D13) (io), U8 I/O112 (2B3) (io), U9 I/O105 (2B8) (io), U10 I/O99 (2B13) (io), V1 I/O191 (2D15) (io), V7 I/O119 (2B2) (io), V8 I/O113 (2B6) (io), V9 I/O106 (2B10) (io), V10 I/O100 (2B14) (io), W5 I/O132 (2B0) (io), W6 I/O127 (2B4) (io), W7 I/O120 (2B5) (io), W8 I/O114 (2B9) (io), W9 I/O107 (2B12) (io), W10 I/O101 (2B15) (io), Y5 I/O133 (2B1) (io), Y7 I/O121 (2B7) (io), Y8 I/O115 (2B11) (io)
part C pins: A1 GND (power), A2 GND (power), A3 GND (power), A6 GND (power), A9 GND (power), A10 GND (power), A11 GND (power), A12 GND (power), A15 GND (power), A18 GND (power), A20 GND (power), B1 GND (power), B20 GND (power), C3 VCC (power), C18 VCC (power), D4 VCC (power), D5 VCC (power), D7 VCC (power), D14 VCC (power), D16 VCC (power), D17 VCC (power), E4 TDO (out), E17 TDI (in), F1 GND (power), F20 GND (power), G4 VCC (power), G17 VCC (power), H1 GND (power), H20 GND (power), K2 I3/CLK3 (in), K19 I0/CLK0 (in), K20 GND (power), L1 GND (power), L2 I2/CLK2 (in), L19 I1/CLK1 (in), N1 GND (power), N20 GND (power), P4 VCC (power), P17 VCC (power), R1 GND (power), R20 GND (power), T4 TMS (in), T17 TCK (in), U4 VCC (power), U5 VCC (power), U7 VCC (power), U14 VCC (power), U16 VCC (power), U17 VCC (power), V3 VCC (power), V18 VCC (power), W1 GND (power), W20 GND (power), Y1 GND (power), Y3 GND (power), Y6 GND (power), Y9 GND (power), Y10 GND (power), Y11 GND (power), Y12 GND (power), Y15 GND (power), Y18 GND (power), Y19 GND (power), Y20 GND (power)

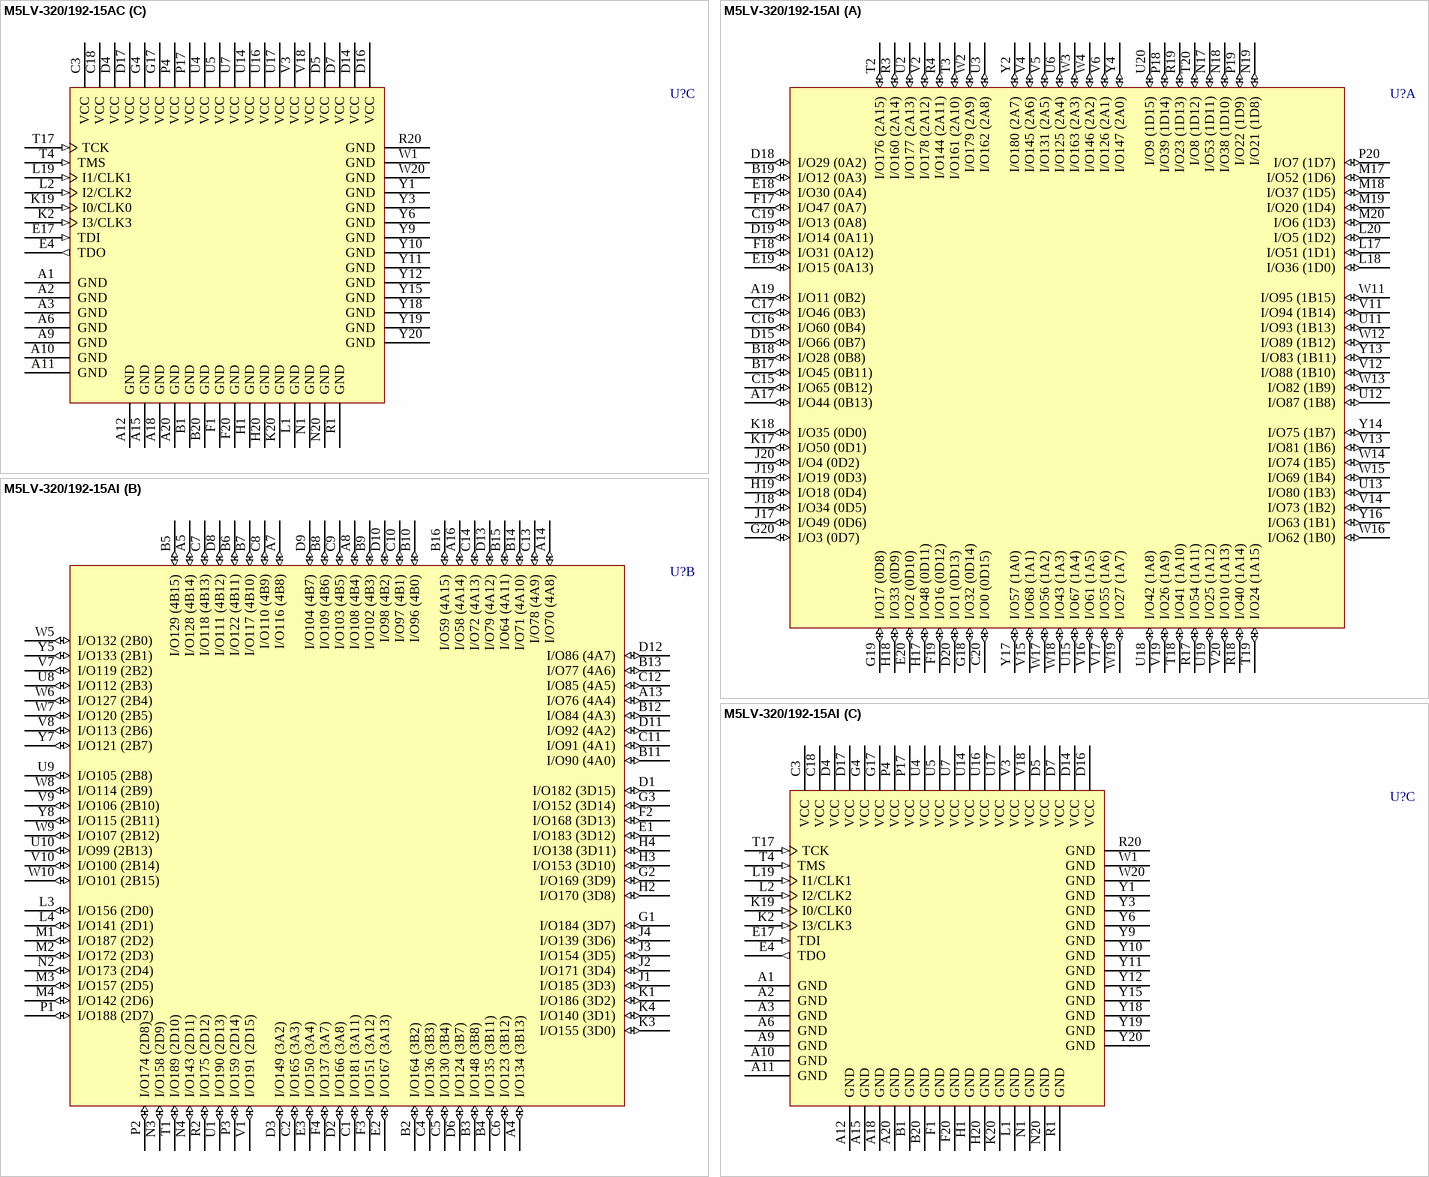
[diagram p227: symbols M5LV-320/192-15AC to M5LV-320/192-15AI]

## M5LV-320/192-15AC
designator U?
High-Density and High-I/O Complex PLD
footprint SBGA256 (BGA, 256-Leads, Body 27x27mm, Pitch 1.27mm)
3D model M5LV-SBGA256 (256-Ball Super Ball Grid Array (SBGA256))
part A pins: A17 I/O44 (0B13) (io), A19 I/O11 (0B2) (io), B17 I/O45 (0B11) (io), B18 I/O28 (0B8) (io), B19 I/O12 (0A3) (io), C15 I/O65 (0B12) (io), C16 I/O60 (0B4) (io), C17 I/O46 (0B3) (io), C19 I/O13 (0A8) (io), C20 I/O0 (0D15) (io), D15 I/O66 (0B7) (io), D18 I/O29 (0A2) (io), D19 I/O14 (0A11) (io), D20 I/O1 (0D13) (io), E18 I/O30 (0A4) (io), E19 I/O15 (0A13) (io), E20 I/O2 (0D10) (io), F17 I/O47 (0A7) (io), F18 I/O31 (0A12) (io), F19 I/O16 (0D12) (io), G18 I/O32 (0D14) (io), G19 I/O17 (0D8) (io), G20 I/O3 (0D7) (io), H17 I/O48 (0D11) (io), H18 I/O33 (0D9) (io), H19 I/O18 (0D4) (io), J17 I/O49 (0D6) (io), J18 I/O34 (0D5) (io), J19 I/O19 (0D3) (io), J20 I/O4 (0D2) (io), K17 I/O50 (0D1) (io), K18 I/O35 (0D0) (io), L17 I/O51 (1D1) (io), L18 I/O36 (1D0) (io), L20 I/O5 (1D2) (io), M17 I/O52 (1D6) (io), M18 I/O37 (1D5) (io), M19 I/O20 (1D4) (io), M20 I/O6 (1D3) (io), N17 I/O53 (1D11) (io), N18 I/O38 (1D10) (io), N19 I/O21 (1D8) (io), P18 I/O39 (1D14) (io), P19 I/O22 (1D9) (io), P20 I/O7 (1D7) (io), R3 I/O160 (2A14) (io), R4 I/O144 (2A11) (io), R17 I/O54 (1A11) (io), R18 I/O40 (1A14) (io), R19 I/O23 (1D13) (io), T2 I/O176 (2A15) (io), T3 I/O161 (2A10) (io), T18 I/O41 (1A10) (io), T19 I/O24 (1A15) (io), T20 I/O8 (1D12) (io), U2 I/O177 (2A13) (io), U3 I/O162 (2A8) (io), U6 I/O125 (2A4) (io), U11 I/O93 (1B13) (io), U12 I/O87 (1B8) (io), U13 I/O80 (1B3) (io), U15 I/O67 (1A4) (io), U18 I/O42 (1A8) (io), U19 I/O25 (1A12) (io), U20 I/O9 (1D15) (io), V2 I/O178 (2A12) (io), V4 I/O145 (2A6) (io), V5 I/O131 (2A5) (io), V6 I/O126 (2A1) (io), V11 I/O94 (1B14) (io), V12 I/O88 (1B10) (io), V13 I/O81 (1B6) (io), V14 I/O73 (1B2) (io), V15 I/O68 (1A1) (io), V16 I/O61 (1A5) (io), V17 I/O55 (1A6) (io), V19 I/O26 (1A9) (io), V20 I/O10 (1A13) (io), W2 I/O179 (2A9) (io), W3 I/O163 (2A3) (io), W4 I/O146 (2A2) (io), W11 I/O95 (1B15) (io), W12 I/O89 (1B12) (io), W13 I/O82 (1B9) (io), W14 I/O74 (1B5) (io), W15 I/O69 (1B4) (io), W16 I/O62 (1B0) (io), W17 I/O56 (1A2) (io), W18 I/O43 (1A3) (io), W19 I/O27 (1A7) (io), Y2 I/O180 (2A7) (io), Y4 I/O147 (2A0) (io), Y13 I/O83 (1B11) (io), Y14 I/O75 (1B7) (io), Y16 I/O63 (1B1) (io), Y17 I/O57 (1A0) (io)
part B pins: A4 I/O134 (3B13) (io), A5 I/O128 (4B14) (io), A7 I/O116 (4B8) (io), A8 I/O108 (4B4) (io), A13 I/O76 (4A4) (io), A14 I/O70 (4A8) (io), A16 I/O58 (4A14) (io), B2 I/O164 (3B2) (io), B3 I/O148 (3B8) (io), B4 I/O135 (3B11) (io), B5 I/O129 (4B15) (io), B6 I/O122 (4B11) (io), B7 I/O117 (4B10) (io), B8 I/O109 (4B6) (io), B9 I/O102 (4B3) (io), B10 I/O96 (4B0) (io), B11 I/O90 (4A0) (io), B12 I/O84 (4A3) (io), B13 I/O77 (4A6) (io), B14 I/O71 (4A10) (io), B15 I/O64 (4A11) (io), B16 I/O59 (4A15) (io), C1 I/O181 (3A11) (io), C2 I/O165 (3A3) (io), C4 I/O136 (3B3) (io), C5 I/O130 (3B4) (io), C6 I/O123 (3B12) (io), C7 I/O118 (4B13) (io), C8 I/O110 (4B9) (io), C9 I/O103 (4B5) (io), C10 I/O97 (4B1) (io), C11 I/O91 (4A1) (io), C12 I/O85 (4A5) (io), C13 I/O78 (4A9) (io), C14 I/O72 (4A13) (io), D1 I/O182 (3D15) (io), D2 I/O166 (3A8) (io), D3 I/O149 (3A2) (io), D6 I/O124 (3B7) (io), D8 I/O111 (4B12) (io), D9 I/O104 (4B7) (io), D10 I/O98 (4B2) (io), D11 I/O92 (4A2) (io), D12 I/O86 (4A7) (io), D13 I/O79 (4A12) (io), E1 I/O183 (3D12) (io), E2 I/O167 (3A13) (io), E3 I/O150 (3A4) (io), F2 I/O168 (3D13) (io), F3 I/O151 (3A12) (io), F4 I/O137 (3A7) (io), G1 I/O184 (3D7) (io), G2 I/O169 (3D9) (io), G3 I/O152 (3D14) (io), H2 I/O170 (3D8) (io), H3 I/O153 (3D10) (io), H4 I/O138 (3D11) (io), J1 I/O185 (3D3) (io), J2 I/O171 (3D4) (io), J3 I/O154 (3D5) (io), J4 I/O139 (3D6) (io), K1 I/O186 (3D2) (io), K3 I/O155 (3D0) (io), K4 I/O140 (3D1) (io), L3 I/O156 (2D0) (io), L4 I/O141 (2D1) (io), M1 I/O187 (2D2) (io), M2 I/O172 (2D3) (io), M3 I/O157 (2D5) (io), M4 I/O142 (2D6) (io), N2 I/O173 (2D4) (io), N3 I/O158 (2D9) (io), N4 I/O143 (2D11) (io), P1 I/O188 (2D7) (io), P2 I/O174 (2D8) (io), P3 I/O159 (2D14) (io), R2 I/O175 (2D12) (io), T1 I/O189 (2D10) (io), U1 I/O190 (2D13) (io), U8 I/O112 (2B3) (io), U9 I/O105 (2B8) (io), U10 I/O99 (2B13) (io), V1 I/O191 (2D15) (io), V7 I/O119 (2B2) (io), V8 I/O113 (2B6) (io), V9 I/O106 (2B10) (io), V10 I/O100 (2B14) (io), W5 I/O132 (2B0) (io), W6 I/O127 (2B4) (io), W7 I/O120 (2B5) (io), W8 I/O114 (2B9) (io), W9 I/O107 (2B12) (io), W10 I/O101 (2B15) (io), Y5 I/O133 (2B1) (io), Y7 I/O121 (2B7) (io), Y8 I/O115 (2B11) (io)
part C pins: A1 GND (power), A2 GND (power), A3 GND (power), A6 GND (power), A9 GND (power), A10 GND (power), A11 GND (power), A12 GND (power), A15 GND (power), A18 GND (power), A20 GND (power), B1 GND (power), B20 GND (power), C3 VCC (power), C18 VCC (power), D4 VCC (power), D5 VCC (power), D7 VCC (power), D14 VCC (power), D16 VCC (power), D17 VCC (power), E4 TDO (out), E17 TDI (in), F1 GND (power), F20 GND (power), G4 VCC (power), G17 VCC (power), H1 GND (power), H20 GND (power), K2 I3/CLK3 (in), K19 I0/CLK0 (in), K20 GND (power), L1 GND (power), L2 I2/CLK2 (in), L19 I1/CLK1 (in), N1 GND (power), N20 GND (power), P4 VCC (power), P17 VCC (power), R1 GND (power), R20 GND (power), T4 TMS (in), T17 TCK (in), U4 VCC (power), U5 VCC (power), U7 VCC (power), U14 VCC (power), U16 VCC (power), U17 VCC (power), V3 VCC (power), V18 VCC (power), W1 GND (power), W20 GND (power), Y1 GND (power), Y3 GND (power), Y6 GND (power), Y9 GND (power), Y10 GND (power), Y11 GND (power), Y12 GND (power), Y15 GND (power), Y18 GND (power), Y19 GND (power), Y20 GND (power)

## M5LV-320/192-15AI
designator U?
High-Density and High-I/O Complex PLD
footprint SBGA256 (BGA, 256-Leads, Body 27x27mm, Pitch 1.27mm)
3D model M5LV-SBGA256 (256-Ball Super Ball Grid Array (SBGA256))
part A pins: A17 I/O44 (0B13) (io), A19 I/O11 (0B2) (io), B17 I/O45 (0B11) (io), B18 I/O28 (0B8) (io), B19 I/O12 (0A3) (io), C15 I/O65 (0B12) (io), C16 I/O60 (0B4) (io), C17 I/O46 (0B3) (io), C19 I/O13 (0A8) (io), C20 I/O0 (0D15) (io), D15 I/O66 (0B7) (io), D18 I/O29 (0A2) (io), D19 I/O14 (0A11) (io), D20 I/O1 (0D13) (io), E18 I/O30 (0A4) (io), E19 I/O15 (0A13) (io), E20 I/O2 (0D10) (io), F17 I/O47 (0A7) (io), F18 I/O31 (0A12) (io), F19 I/O16 (0D12) (io), G18 I/O32 (0D14) (io), G19 I/O17 (0D8) (io), G20 I/O3 (0D7) (io), H17 I/O48 (0D11) (io), H18 I/O33 (0D9) (io), H19 I/O18 (0D4) (io), J17 I/O49 (0D6) (io), J18 I/O34 (0D5) (io), J19 I/O19 (0D3) (io), J20 I/O4 (0D2) (io), K17 I/O50 (0D1) (io), K18 I/O35 (0D0) (io), L17 I/O51 (1D1) (io), L18 I/O36 (1D0) (io), L20 I/O5 (1D2) (io), M17 I/O52 (1D6) (io), M18 I/O37 (1D5) (io), M19 I/O20 (1D4) (io), M20 I/O6 (1D3) (io), N17 I/O53 (1D11) (io), N18 I/O38 (1D10) (io), N19 I/O21 (1D8) (io), P18 I/O39 (1D14) (io), P19 I/O22 (1D9) (io), P20 I/O7 (1D7) (io), R3 I/O160 (2A14) (io), R4 I/O144 (2A11) (io), R17 I/O54 (1A11) (io), R18 I/O40 (1A14) (io), R19 I/O23 (1D13) (io), T2 I/O176 (2A15) (io), T3 I/O161 (2A10) (io), T18 I/O41 (1A10) (io), T19 I/O24 (1A15) (io), T20 I/O8 (1D12) (io), U2 I/O177 (2A13) (io), U3 I/O162 (2A8) (io), U6 I/O125 (2A4) (io), U11 I/O93 (1B13) (io), U12 I/O87 (1B8) (io), U13 I/O80 (1B3) (io), U15 I/O67 (1A4) (io), U18 I/O42 (1A8) (io), U19 I/O25 (1A12) (io), U20 I/O9 (1D15) (io), V2 I/O178 (2A12) (io), V4 I/O145 (2A6) (io), V5 I/O131 (2A5) (io), V6 I/O126 (2A1) (io), V11 I/O94 (1B14) (io), V12 I/O88 (1B10) (io), V13 I/O81 (1B6) (io), V14 I/O73 (1B2) (io), V15 I/O68 (1A1) (io), V16 I/O61 (1A5) (io), V17 I/O55 (1A6) (io), V19 I/O26 (1A9) (io), V20 I/O10 (1A13) (io), W2 I/O179 (2A9) (io), W3 I/O163 (2A3) (io), W4 I/O146 (2A2) (io), W11 I/O95 (1B15) (io), W12 I/O89 (1B12) (io), W13 I/O82 (1B9) (io), W14 I/O74 (1B5) (io), W15 I/O69 (1B4) (io), W16 I/O62 (1B0) (io), W17 I/O56 (1A2) (io), W18 I/O43 (1A3) (io), W19 I/O27 (1A7) (io), Y2 I/O180 (2A7) (io), Y4 I/O147 (2A0) (io), Y13 I/O83 (1B11) (io), Y14 I/O75 (1B7) (io), Y16 I/O63 (1B1) (io), Y17 I/O57 (1A0) (io)
part B pins: A4 I/O134 (3B13) (io), A5 I/O128 (4B14) (io), A7 I/O116 (4B8) (io), A8 I/O108 (4B4) (io), A13 I/O76 (4A4) (io), A14 I/O70 (4A8) (io), A16 I/O58 (4A14) (io), B2 I/O164 (3B2) (io), B3 I/O148 (3B8) (io), B4 I/O135 (3B11) (io), B5 I/O129 (4B15) (io), B6 I/O122 (4B11) (io), B7 I/O117 (4B10) (io), B8 I/O109 (4B6) (io), B9 I/O102 (4B3) (io), B10 I/O96 (4B0) (io), B11 I/O90 (4A0) (io), B12 I/O84 (4A3) (io), B13 I/O77 (4A6) (io), B14 I/O71 (4A10) (io), B15 I/O64 (4A11) (io), B16 I/O59 (4A15) (io), C1 I/O181 (3A11) (io), C2 I/O165 (3A3) (io), C4 I/O136 (3B3) (io), C5 I/O130 (3B4) (io), C6 I/O123 (3B12) (io), C7 I/O118 (4B13) (io), C8 I/O110 (4B9) (io), C9 I/O103 (4B5) (io), C10 I/O97 (4B1) (io), C11 I/O91 (4A1) (io), C12 I/O85 (4A5) (io), C13 I/O78 (4A9) (io), C14 I/O72 (4A13) (io), D1 I/O182 (3D15) (io), D2 I/O166 (3A8) (io), D3 I/O149 (3A2) (io), D6 I/O124 (3B7) (io), D8 I/O111 (4B12) (io), D9 I/O104 (4B7) (io), D10 I/O98 (4B2) (io), D11 I/O92 (4A2) (io), D12 I/O86 (4A7) (io), D13 I/O79 (4A12) (io), E1 I/O183 (3D12) (io), E2 I/O167 (3A13) (io), E3 I/O150 (3A4) (io), F2 I/O168 (3D13) (io), F3 I/O151 (3A12) (io), F4 I/O137 (3A7) (io), G1 I/O184 (3D7) (io), G2 I/O169 (3D9) (io), G3 I/O152 (3D14) (io), H2 I/O170 (3D8) (io), H3 I/O153 (3D10) (io), H4 I/O138 (3D11) (io), J1 I/O185 (3D3) (io), J2 I/O171 (3D4) (io), J3 I/O154 (3D5) (io), J4 I/O139 (3D6) (io), K1 I/O186 (3D2) (io), K3 I/O155 (3D0) (io), K4 I/O140 (3D1) (io), L3 I/O156 (2D0) (io), L4 I/O141 (2D1) (io), M1 I/O187 (2D2) (io), M2 I/O172 (2D3) (io), M3 I/O157 (2D5) (io), M4 I/O142 (2D6) (io), N2 I/O173 (2D4) (io), N3 I/O158 (2D9) (io), N4 I/O143 (2D11) (io), P1 I/O188 (2D7) (io), P2 I/O174 (2D8) (io), P3 I/O159 (2D14) (io), R2 I/O175 (2D12) (io), T1 I/O189 (2D10) (io), U1 I/O190 (2D13) (io), U8 I/O112 (2B3) (io), U9 I/O105 (2B8) (io), U10 I/O99 (2B13) (io), V1 I/O191 (2D15) (io), V7 I/O119 (2B2) (io), V8 I/O113 (2B6) (io), V9 I/O106 (2B10) (io), V10 I/O100 (2B14) (io), W5 I/O132 (2B0) (io), W6 I/O127 (2B4) (io), W7 I/O120 (2B5) (io), W8 I/O114 (2B9) (io), W9 I/O107 (2B12) (io), W10 I/O101 (2B15) (io), Y5 I/O133 (2B1) (io), Y7 I/O121 (2B7) (io), Y8 I/O115 (2B11) (io)
part C pins: A1 GND (power), A2 GND (power), A3 GND (power), A6 GND (power), A9 GND (power), A10 GND (power), A11 GND (power), A12 GND (power), A15 GND (power), A18 GND (power), A20 GND (power), B1 GND (power), B20 GND (power), C3 VCC (power), C18 VCC (power), D4 VCC (power), D5 VCC (power), D7 VCC (power), D14 VCC (power), D16 VCC (power), D17 VCC (power), E4 TDO (out), E17 TDI (in), F1 GND (power), F20 GND (power), G4 VCC (power), G17 VCC (power), H1 GND (power), H20 GND (power), K2 I3/CLK3 (in), K19 I0/CLK0 (in), K20 GND (power), L1 GND (power), L2 I2/CLK2 (in), L19 I1/CLK1 (in), N1 GND (power), N20 GND (power), P4 VCC (power), P17 VCC (power), R1 GND (power), R20 GND (power), T4 TMS (in), T17 TCK (in), U4 VCC (power), U5 VCC (power), U7 VCC (power), U14 VCC (power), U16 VCC (power), U17 VCC (power), V3 VCC (power), V18 VCC (power), W1 GND (power), W20 GND (power), Y1 GND (power), Y3 GND (power), Y6 GND (power), Y9 GND (power), Y10 GND (power), Y11 GND (power), Y12 GND (power), Y15 GND (power), Y18 GND (power), Y19 GND (power), Y20 GND (power)

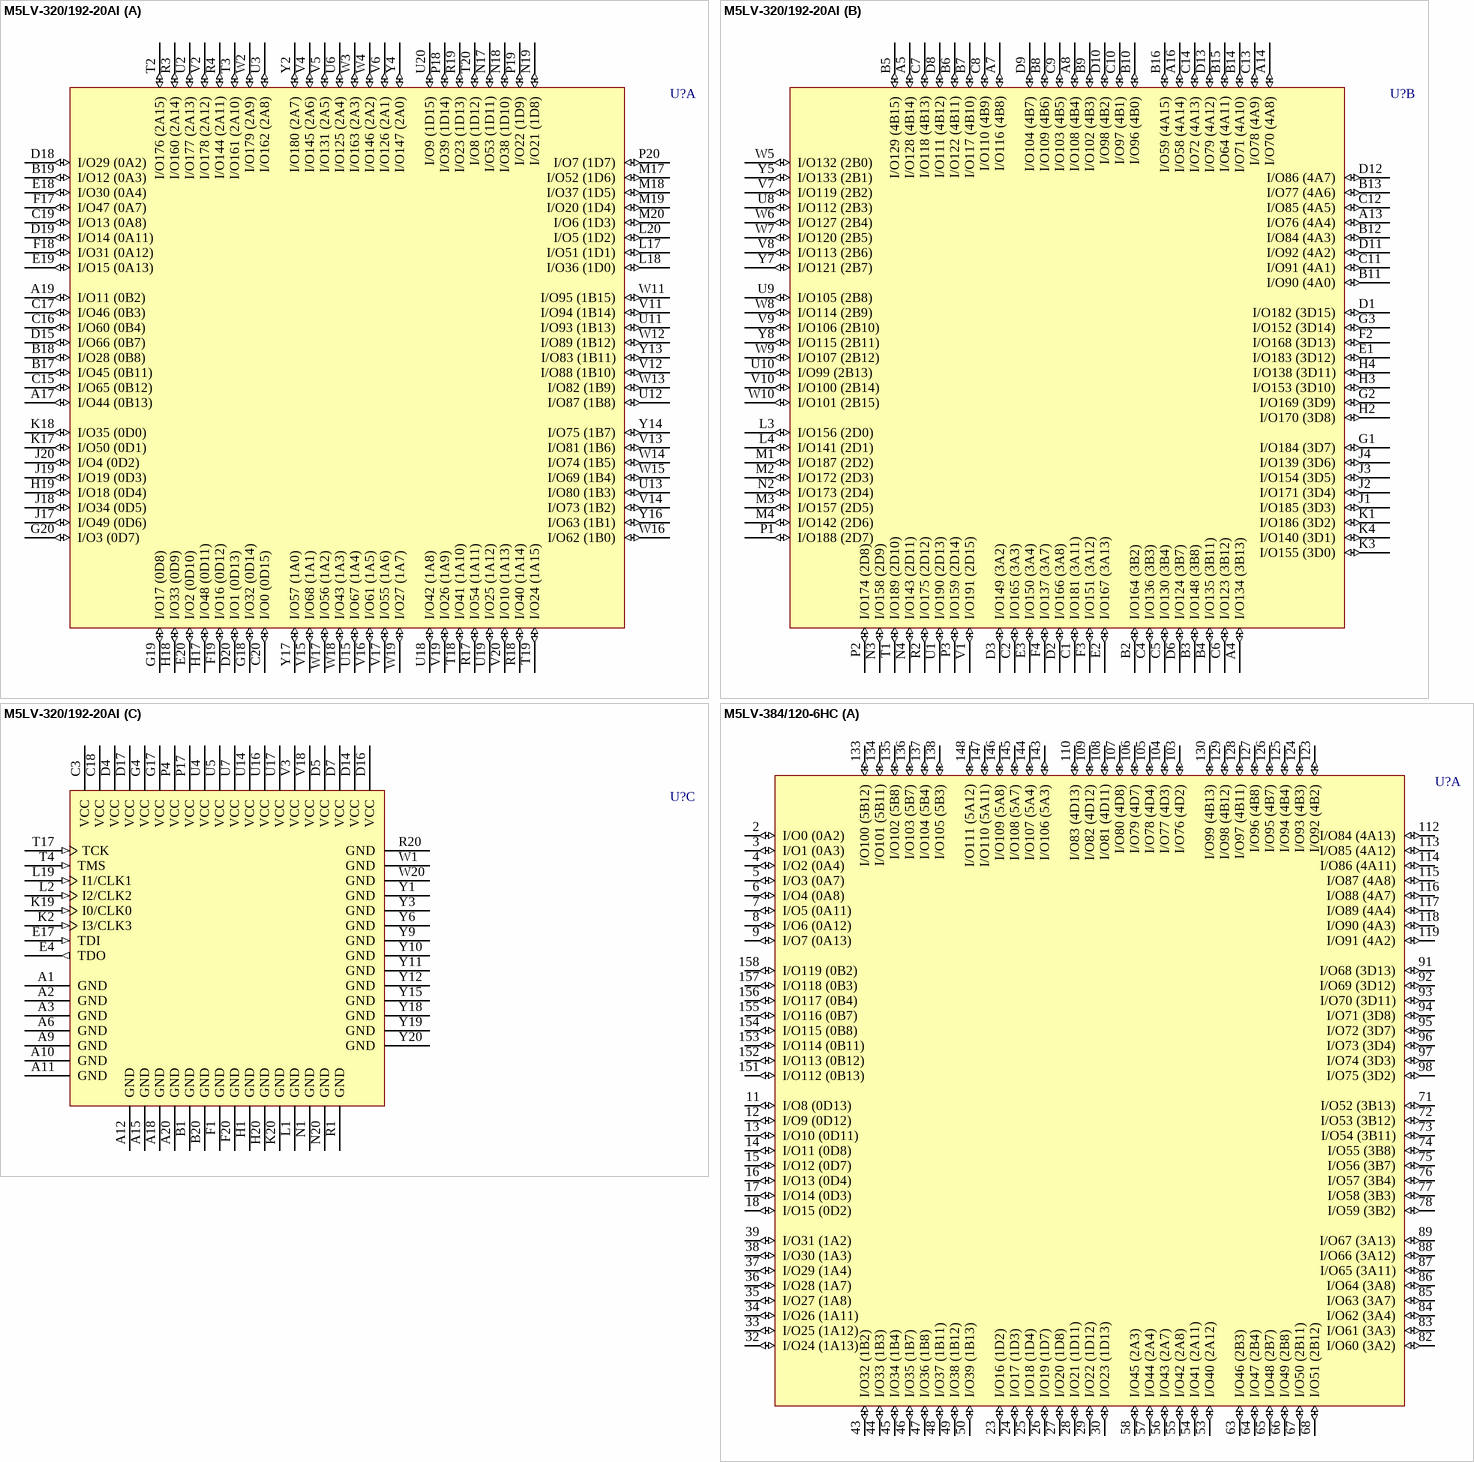
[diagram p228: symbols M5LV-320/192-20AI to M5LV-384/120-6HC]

## M5LV-320/192-20AI
designator U?
High-Density and High-I/O Complex PLD
footprint SBGA256 (BGA, 256-Leads, Body 27x27mm, Pitch 1.27mm)
3D model M5LV-SBGA256 (256-Ball Super Ball Grid Array (SBGA256))
part A pins: A17 I/O44 (0B13) (io), A19 I/O11 (0B2) (io), B17 I/O45 (0B11) (io), B18 I/O28 (0B8) (io), B19 I/O12 (0A3) (io), C15 I/O65 (0B12) (io), C16 I/O60 (0B4) (io), C17 I/O46 (0B3) (io), C19 I/O13 (0A8) (io), C20 I/O0 (0D15) (io), D15 I/O66 (0B7) (io), D18 I/O29 (0A2) (io), D19 I/O14 (0A11) (io), D20 I/O1 (0D13) (io), E18 I/O30 (0A4) (io), E19 I/O15 (0A13) (io), E20 I/O2 (0D10) (io), F17 I/O47 (0A7) (io), F18 I/O31 (0A12) (io), F19 I/O16 (0D12) (io), G18 I/O32 (0D14) (io), G19 I/O17 (0D8) (io), G20 I/O3 (0D7) (io), H17 I/O48 (0D11) (io), H18 I/O33 (0D9) (io), H19 I/O18 (0D4) (io), J17 I/O49 (0D6) (io), J18 I/O34 (0D5) (io), J19 I/O19 (0D3) (io), J20 I/O4 (0D2) (io), K17 I/O50 (0D1) (io), K18 I/O35 (0D0) (io), L17 I/O51 (1D1) (io), L18 I/O36 (1D0) (io), L20 I/O5 (1D2) (io), M17 I/O52 (1D6) (io), M18 I/O37 (1D5) (io), M19 I/O20 (1D4) (io), M20 I/O6 (1D3) (io), N17 I/O53 (1D11) (io), N18 I/O38 (1D10) (io), N19 I/O21 (1D8) (io), P18 I/O39 (1D14) (io), P19 I/O22 (1D9) (io), P20 I/O7 (1D7) (io), R3 I/O160 (2A14) (io), R4 I/O144 (2A11) (io), R17 I/O54 (1A11) (io), R18 I/O40 (1A14) (io), R19 I/O23 (1D13) (io), T2 I/O176 (2A15) (io), T3 I/O161 (2A10) (io), T18 I/O41 (1A10) (io), T19 I/O24 (1A15) (io), T20 I/O8 (1D12) (io), U2 I/O177 (2A13) (io), U3 I/O162 (2A8) (io), U6 I/O125 (2A4) (io), U11 I/O93 (1B13) (io), U12 I/O87 (1B8) (io), U13 I/O80 (1B3) (io), U15 I/O67 (1A4) (io), U18 I/O42 (1A8) (io), U19 I/O25 (1A12) (io), U20 I/O9 (1D15) (io), V2 I/O178 (2A12) (io), V4 I/O145 (2A6) (io), V5 I/O131 (2A5) (io), V6 I/O126 (2A1) (io), V11 I/O94 (1B14) (io), V12 I/O88 (1B10) (io), V13 I/O81 (1B6) (io), V14 I/O73 (1B2) (io), V15 I/O68 (1A1) (io), V16 I/O61 (1A5) (io), V17 I/O55 (1A6) (io), V19 I/O26 (1A9) (io), V20 I/O10 (1A13) (io), W2 I/O179 (2A9) (io), W3 I/O163 (2A3) (io), W4 I/O146 (2A2) (io), W11 I/O95 (1B15) (io), W12 I/O89 (1B12) (io), W13 I/O82 (1B9) (io), W14 I/O74 (1B5) (io), W15 I/O69 (1B4) (io), W16 I/O62 (1B0) (io), W17 I/O56 (1A2) (io), W18 I/O43 (1A3) (io), W19 I/O27 (1A7) (io), Y2 I/O180 (2A7) (io), Y4 I/O147 (2A0) (io), Y13 I/O83 (1B11) (io), Y14 I/O75 (1B7) (io), Y16 I/O63 (1B1) (io), Y17 I/O57 (1A0) (io)
part B pins: A4 I/O134 (3B13) (io), A5 I/O128 (4B14) (io), A7 I/O116 (4B8) (io), A8 I/O108 (4B4) (io), A13 I/O76 (4A4) (io), A14 I/O70 (4A8) (io), A16 I/O58 (4A14) (io), B2 I/O164 (3B2) (io), B3 I/O148 (3B8) (io), B4 I/O135 (3B11) (io), B5 I/O129 (4B15) (io), B6 I/O122 (4B11) (io), B7 I/O117 (4B10) (io), B8 I/O109 (4B6) (io), B9 I/O102 (4B3) (io), B10 I/O96 (4B0) (io), B11 I/O90 (4A0) (io), B12 I/O84 (4A3) (io), B13 I/O77 (4A6) (io), B14 I/O71 (4A10) (io), B15 I/O64 (4A11) (io), B16 I/O59 (4A15) (io), C1 I/O181 (3A11) (io), C2 I/O165 (3A3) (io), C4 I/O136 (3B3) (io), C5 I/O130 (3B4) (io), C6 I/O123 (3B12) (io), C7 I/O118 (4B13) (io), C8 I/O110 (4B9) (io), C9 I/O103 (4B5) (io), C10 I/O97 (4B1) (io), C11 I/O91 (4A1) (io), C12 I/O85 (4A5) (io), C13 I/O78 (4A9) (io), C14 I/O72 (4A13) (io), D1 I/O182 (3D15) (io), D2 I/O166 (3A8) (io), D3 I/O149 (3A2) (io), D6 I/O124 (3B7) (io), D8 I/O111 (4B12) (io), D9 I/O104 (4B7) (io), D10 I/O98 (4B2) (io), D11 I/O92 (4A2) (io), D12 I/O86 (4A7) (io), D13 I/O79 (4A12) (io), E1 I/O183 (3D12) (io), E2 I/O167 (3A13) (io), E3 I/O150 (3A4) (io), F2 I/O168 (3D13) (io), F3 I/O151 (3A12) (io), F4 I/O137 (3A7) (io), G1 I/O184 (3D7) (io), G2 I/O169 (3D9) (io), G3 I/O152 (3D14) (io), H2 I/O170 (3D8) (io), H3 I/O153 (3D10) (io), H4 I/O138 (3D11) (io), J1 I/O185 (3D3) (io), J2 I/O171 (3D4) (io), J3 I/O154 (3D5) (io), J4 I/O139 (3D6) (io), K1 I/O186 (3D2) (io), K3 I/O155 (3D0) (io), K4 I/O140 (3D1) (io), L3 I/O156 (2D0) (io), L4 I/O141 (2D1) (io), M1 I/O187 (2D2) (io), M2 I/O172 (2D3) (io), M3 I/O157 (2D5) (io), M4 I/O142 (2D6) (io), N2 I/O173 (2D4) (io), N3 I/O158 (2D9) (io), N4 I/O143 (2D11) (io), P1 I/O188 (2D7) (io), P2 I/O174 (2D8) (io), P3 I/O159 (2D14) (io), R2 I/O175 (2D12) (io), T1 I/O189 (2D10) (io), U1 I/O190 (2D13) (io), U8 I/O112 (2B3) (io), U9 I/O105 (2B8) (io), U10 I/O99 (2B13) (io), V1 I/O191 (2D15) (io), V7 I/O119 (2B2) (io), V8 I/O113 (2B6) (io), V9 I/O106 (2B10) (io), V10 I/O100 (2B14) (io), W5 I/O132 (2B0) (io), W6 I/O127 (2B4) (io), W7 I/O120 (2B5) (io), W8 I/O114 (2B9) (io), W9 I/O107 (2B12) (io), W10 I/O101 (2B15) (io), Y5 I/O133 (2B1) (io), Y7 I/O121 (2B7) (io), Y8 I/O115 (2B11) (io)
part C pins: A1 GND (power), A2 GND (power), A3 GND (power), A6 GND (power), A9 GND (power), A10 GND (power), A11 GND (power), A12 GND (power), A15 GND (power), A18 GND (power), A20 GND (power), B1 GND (power), B20 GND (power), C3 VCC (power), C18 VCC (power), D4 VCC (power), D5 VCC (power), D7 VCC (power), D14 VCC (power), D16 VCC (power), D17 VCC (power), E4 TDO (out), E17 TDI (in), F1 GND (power), F20 GND (power), G4 VCC (power), G17 VCC (power), H1 GND (power), H20 GND (power), K2 I3/CLK3 (in), K19 I0/CLK0 (in), K20 GND (power), L1 GND (power), L2 I2/CLK2 (in), L19 I1/CLK1 (in), N1 GND (power), N20 GND (power), P4 VCC (power), P17 VCC (power), R1 GND (power), R20 GND (power), T4 TMS (in), T17 TCK (in), U4 VCC (power), U5 VCC (power), U7 VCC (power), U14 VCC (power), U16 VCC (power), U17 VCC (power), V3 VCC (power), V18 VCC (power), W1 GND (power), W20 GND (power), Y1 GND (power), Y3 GND (power), Y6 GND (power), Y9 GND (power), Y10 GND (power), Y11 GND (power), Y12 GND (power), Y15 GND (power), Y18 GND (power), Y19 GND (power), Y20 GND (power)

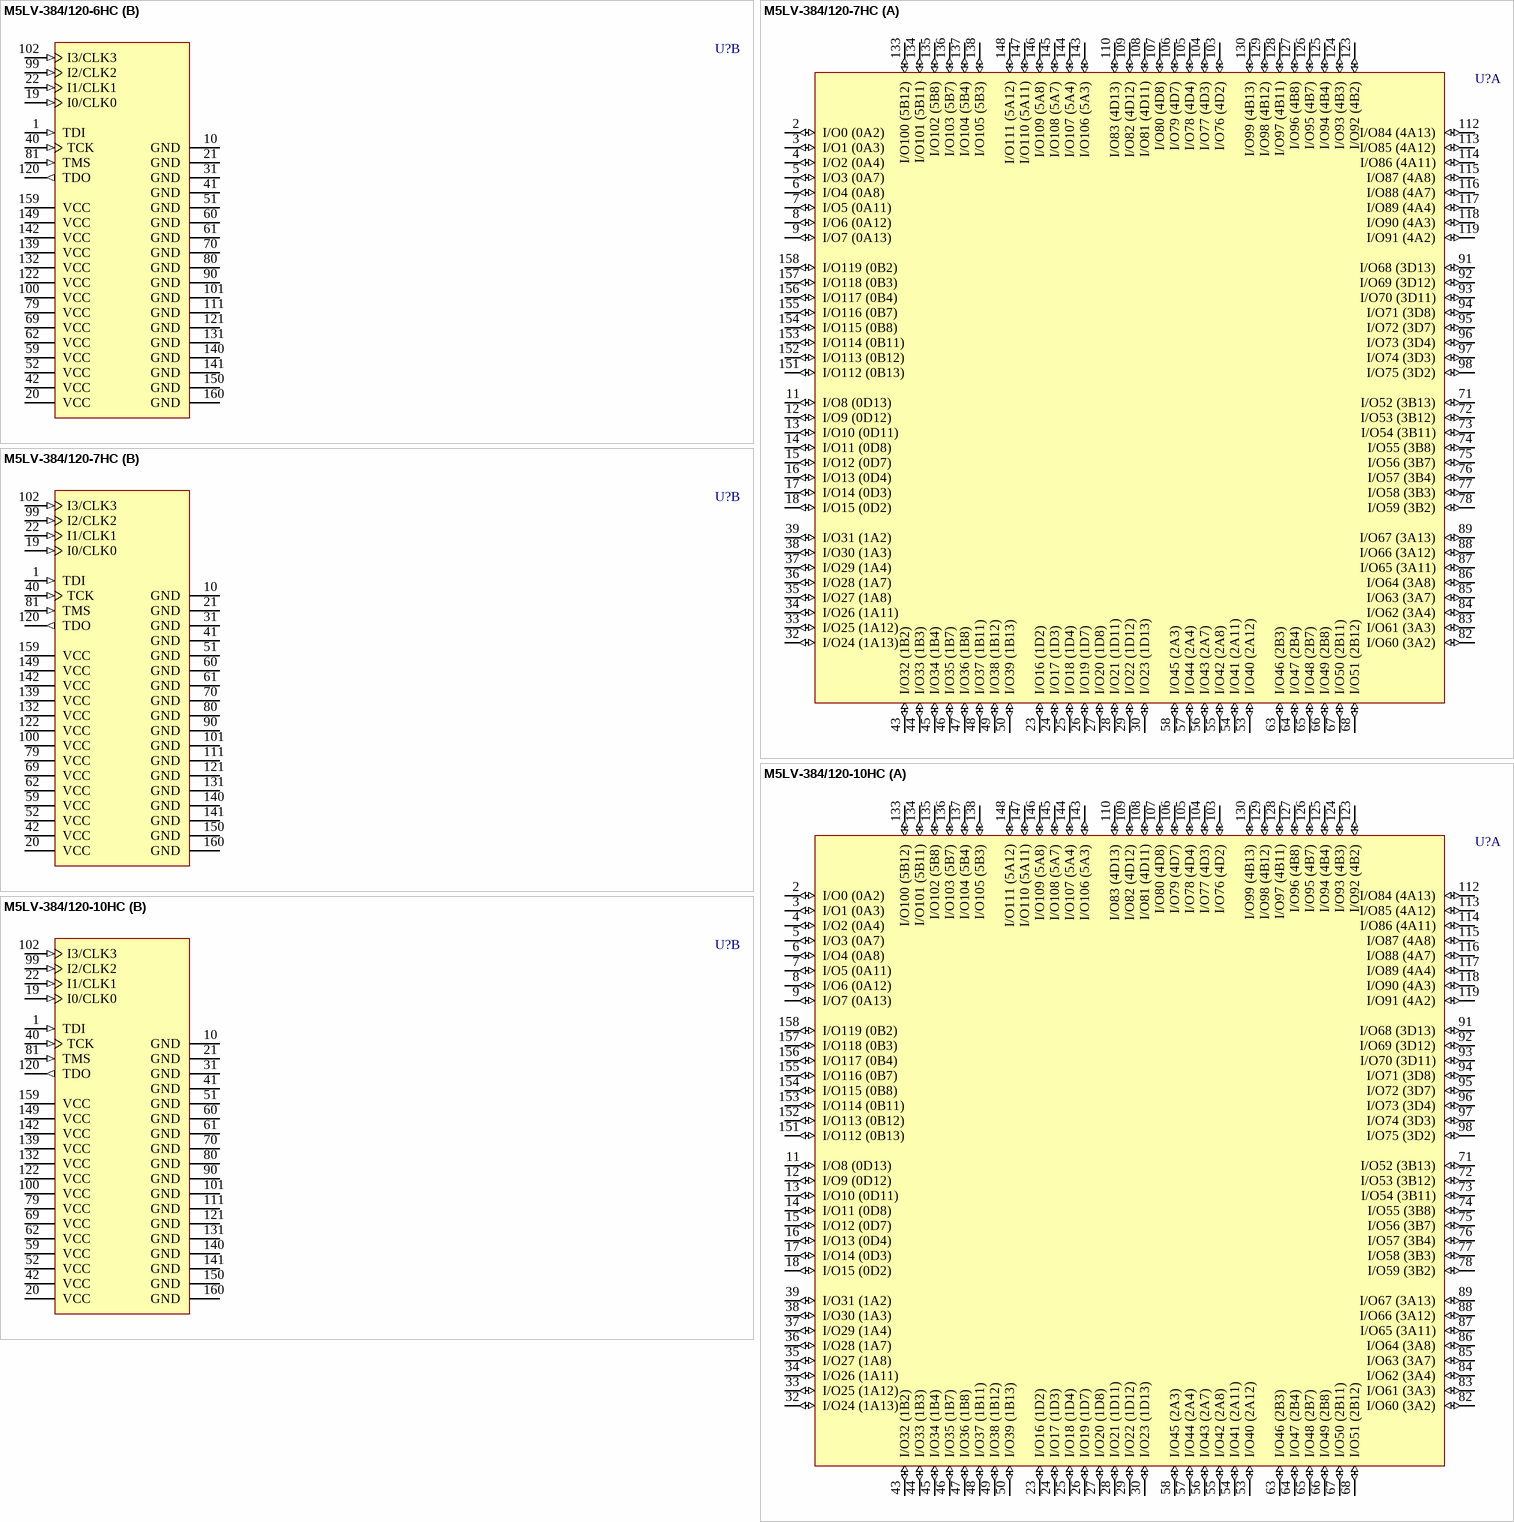
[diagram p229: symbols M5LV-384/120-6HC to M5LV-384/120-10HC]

## M5LV-384/120-6HC
designator U?
High-Density and High-I/O Complex PLD
footprint MQFP160_N (QFP, 160-Leads, Body 27.7 x 27.7mm, Pitch 0.65mm, IPC Medium Density)
footprint MQFP160_L (QFP, 160-Leads, Body 27.7 x 27.7mm, Pitch 0.65mm, IPC High Density)
footprint MQFP160_M (QFP, 160-Leads, Body 27.7 x 27.7mm, Pitch 0.65mm, IPC Low Density)
3D model M5LV-MQFP160 (160-Pin Quad Flat Pack 0.65 mm Pitch)
part A pins: 2 I/O0 (0A2) (io), 3 I/O1 (0A3) (io), 4 I/O2 (0A4) (io), 5 I/O3 (0A7) (io), 6 I/O4 (0A8) (io), 7 I/O5 (0A11) (io), 8 I/O6 (0A12) (io), 9 I/O7 (0A13) (io), 11 I/O8 (0D13) (io), 12 I/O9 (0D12) (io), 13 I/O10 (0D11) (io), 14 I/O11 (0D8) (io), 15 I/O12 (0D7) (io), 16 I/O13 (0D4) (io), 17 I/O14 (0D3) (io), 18 I/O15 (0D2) (io), 23 I/O16 (1D2) (io), 24 I/O17 (1D3) (io), 25 I/O18 (1D4) (io), 26 I/O19 (1D7) (io), 27 I/O20 (1D8) (io), 28 I/O21 (1D11) (io), 29 I/O22 (1D12) (io), 30 I/O23 (1D13) (io), 32 I/O24 (1A13) (io), 33 I/O25 (1A12) (io), 34 I/O26 (1A11) (io), 35 I/O27 (1A8) (io), 36 I/O28 (1A7) (io), 37 I/O29 (1A4) (io), 38 I/O30 (1A3) (io), 39 I/O31 (1A2) (io), 43 I/O32 (1B2) (io), 44 I/O33 (1B3) (io), 45 I/O34 (1B4) (io), 46 I/O35 (1B7) (io), 47 I/O36 (1B8) (io), 48 I/O37 (1B11) (io), 49 I/O38 (1B12) (io), 50 I/O39 (1B13) (io), 53 I/O40 (2A12) (io), 54 I/O41 (2A11) (io), 55 I/O42 (2A8) (io), 56 I/O43 (2A7) (io), 57 I/O44 (2A4) (io), 58 I/O45 (2A3) (io), 63 I/O46 (2B3) (io), 64 I/O47 (2B4) (io), 65 I/O48 (2B7) (io), 66 I/O49 (2B8) (io), 67 I/O50 (2B11) (io), 68 I/O51 (2B12) (io), 71 I/O52 (3B13) (io), 72 I/O53 (3B12) (io), 73 I/O54 (3B11) (io), 74 I/O55 (3B8) (io), 75 I/O56 (3B7) (io), 76 I/O57 (3B4) (io), 77 I/O58 (3B3) (io), 78 I/O59 (3B2) (io), 82 I/O60 (3A2) (io), 83 I/O61 (3A3) (io), 84 I/O62 (3A4) (io), 85 I/O63 (3A7) (io), 86 I/O64 (3A8) (io), 87 I/O65 (3A11) (io), 88 I/O66 (3A12) (io), 89 I/O67 (3A13) (io), 91 I/O68 (3D13) (io), 92 I/O69 (3D12) (io), 93 I/O70 (3D11) (io), 94 I/O71 (3D8) (io), 95 I/O72 (3D7) (io), 96 I/O73 (3D4) (io), 97 I/O74 (3D3) (io), 98 I/O75 (3D2) (io), 103 I/O76 (4D2) (io), 104 I/O77 (4D3) (io), 105 I/O78 (4D4) (io), 106 I/O79 (4D7) (io), 107 I/O80 (4D8) (io), 108 I/O81 (4D11) (io), 109 I/O82 (4D12) (io), 110 I/O83 (4D13) (io), 112 I/O84 (4A13) (io), 113 I/O85 (4A12) (io), 114 I/O86 (4A11) (io), 115 I/O87 (4A8) (io), 116 I/O88 (4A7) (io), 117 I/O89 (4A4) (io), 118 I/O90 (4A3) (io), 119 I/O91 (4A2) (io), 123 I/O92 (4B2) (io), 124 I/O93 (4B3) (io), 125 I/O94 (4B4) (io), 126 I/O95 (4B7) (io), 127 I/O96 (4B8) (io), 128 I/O97 (4B11) (io), 129 I/O98 (4B12) (io), 130 I/O99 (4B13) (io), 133 I/O100 (5B12) (io), 134 I/O101 (5B11) (io), 135 I/O102 (5B8) (io), 136 I/O103 (5B7) (io), 137 I/O104 (5B4) (io), 138 I/O105 (5B3) (io), 143 I/O106 (5A3) (io), 144 I/O107 (5A4) (io), 145 I/O108 (5A7) (io), 146 I/O109 (5A8) (io), 147 I/O110 (5A11) (io), 148 I/O111 (5A12) (io), 151 I/O112 (0B13) (io), 152 I/O113 (0B12) (io), 153 I/O114 (0B11) (io), 154 I/O115 (0B8) (io), 155 I/O116 (0B7) (io), 156 I/O117 (0B4) (io), 157 I/O118 (0B3) (io), 158 I/O119 (0B2) (io)
part B pins: 1 TDI (in), 10 GND (power), 19 I0/CLK0 (in), 20 VCC (power), 21 GND (power), 22 I1/CLK1 (in), 31 GND (power), 40 TCK (in), 41 GND (power), 42 VCC (power), 51 GND (power), 52 VCC (power), 59 VCC (power), 60 GND (power), 61 GND (power), 62 VCC (power), 69 VCC (power), 70 GND (power), 79 VCC (power), 80 GND (power), 81 TMS (in), 90 GND (power), 99 I2/CLK2 (in), 100 VCC (power), 101 GND (power), 102 I3/CLK3 (in), 111 GND (power), 120 TDO (out), 121 GND (power), 122 VCC (power), 131 GND (power), 132 VCC (power), 139 VCC (power), 140 GND (power), 141 GND (power), 142 VCC (power), 149 VCC (power), 150 GND (power), 159 VCC (power), 160 GND (power)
